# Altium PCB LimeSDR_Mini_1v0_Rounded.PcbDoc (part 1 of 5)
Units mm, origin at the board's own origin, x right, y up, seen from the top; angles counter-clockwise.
Board outline 69.3 x 52.3 mm, 8 copper layers (Top, L2, L3, L4, L5, L6, L7, Bottom), stack 1.555 mm thick; 371 components, 281 nets, 1644 pads, 778 vias.
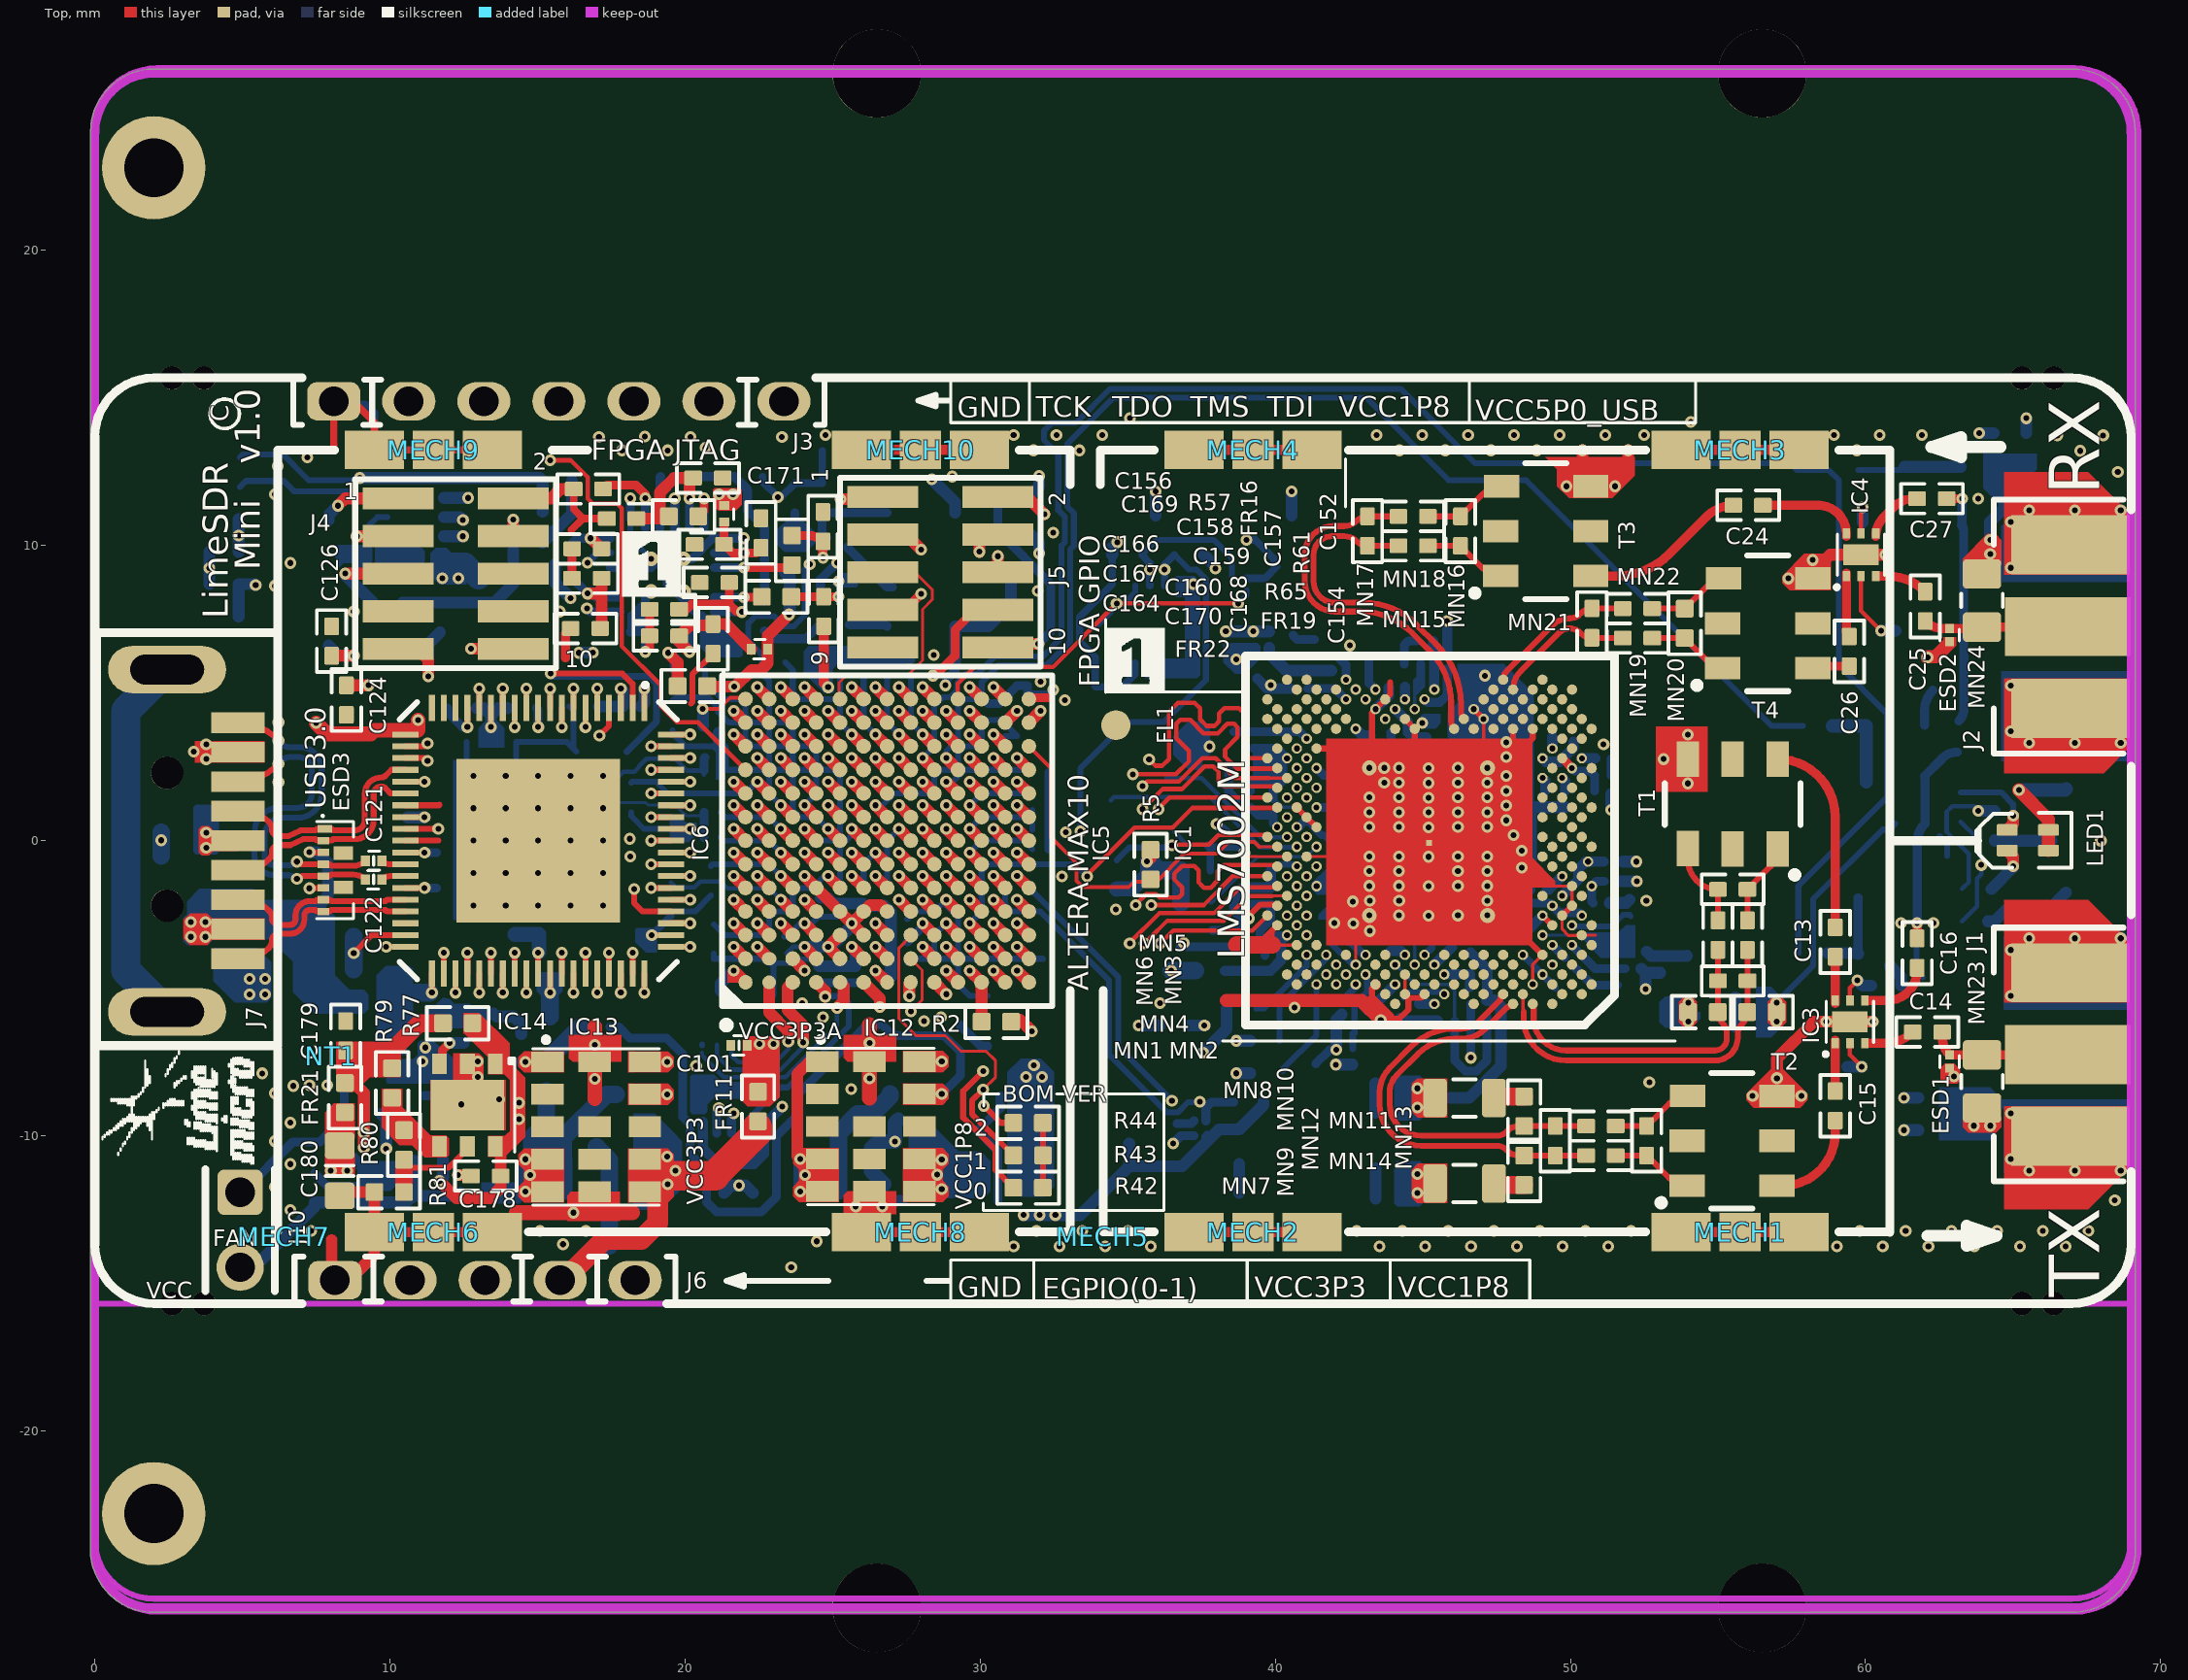
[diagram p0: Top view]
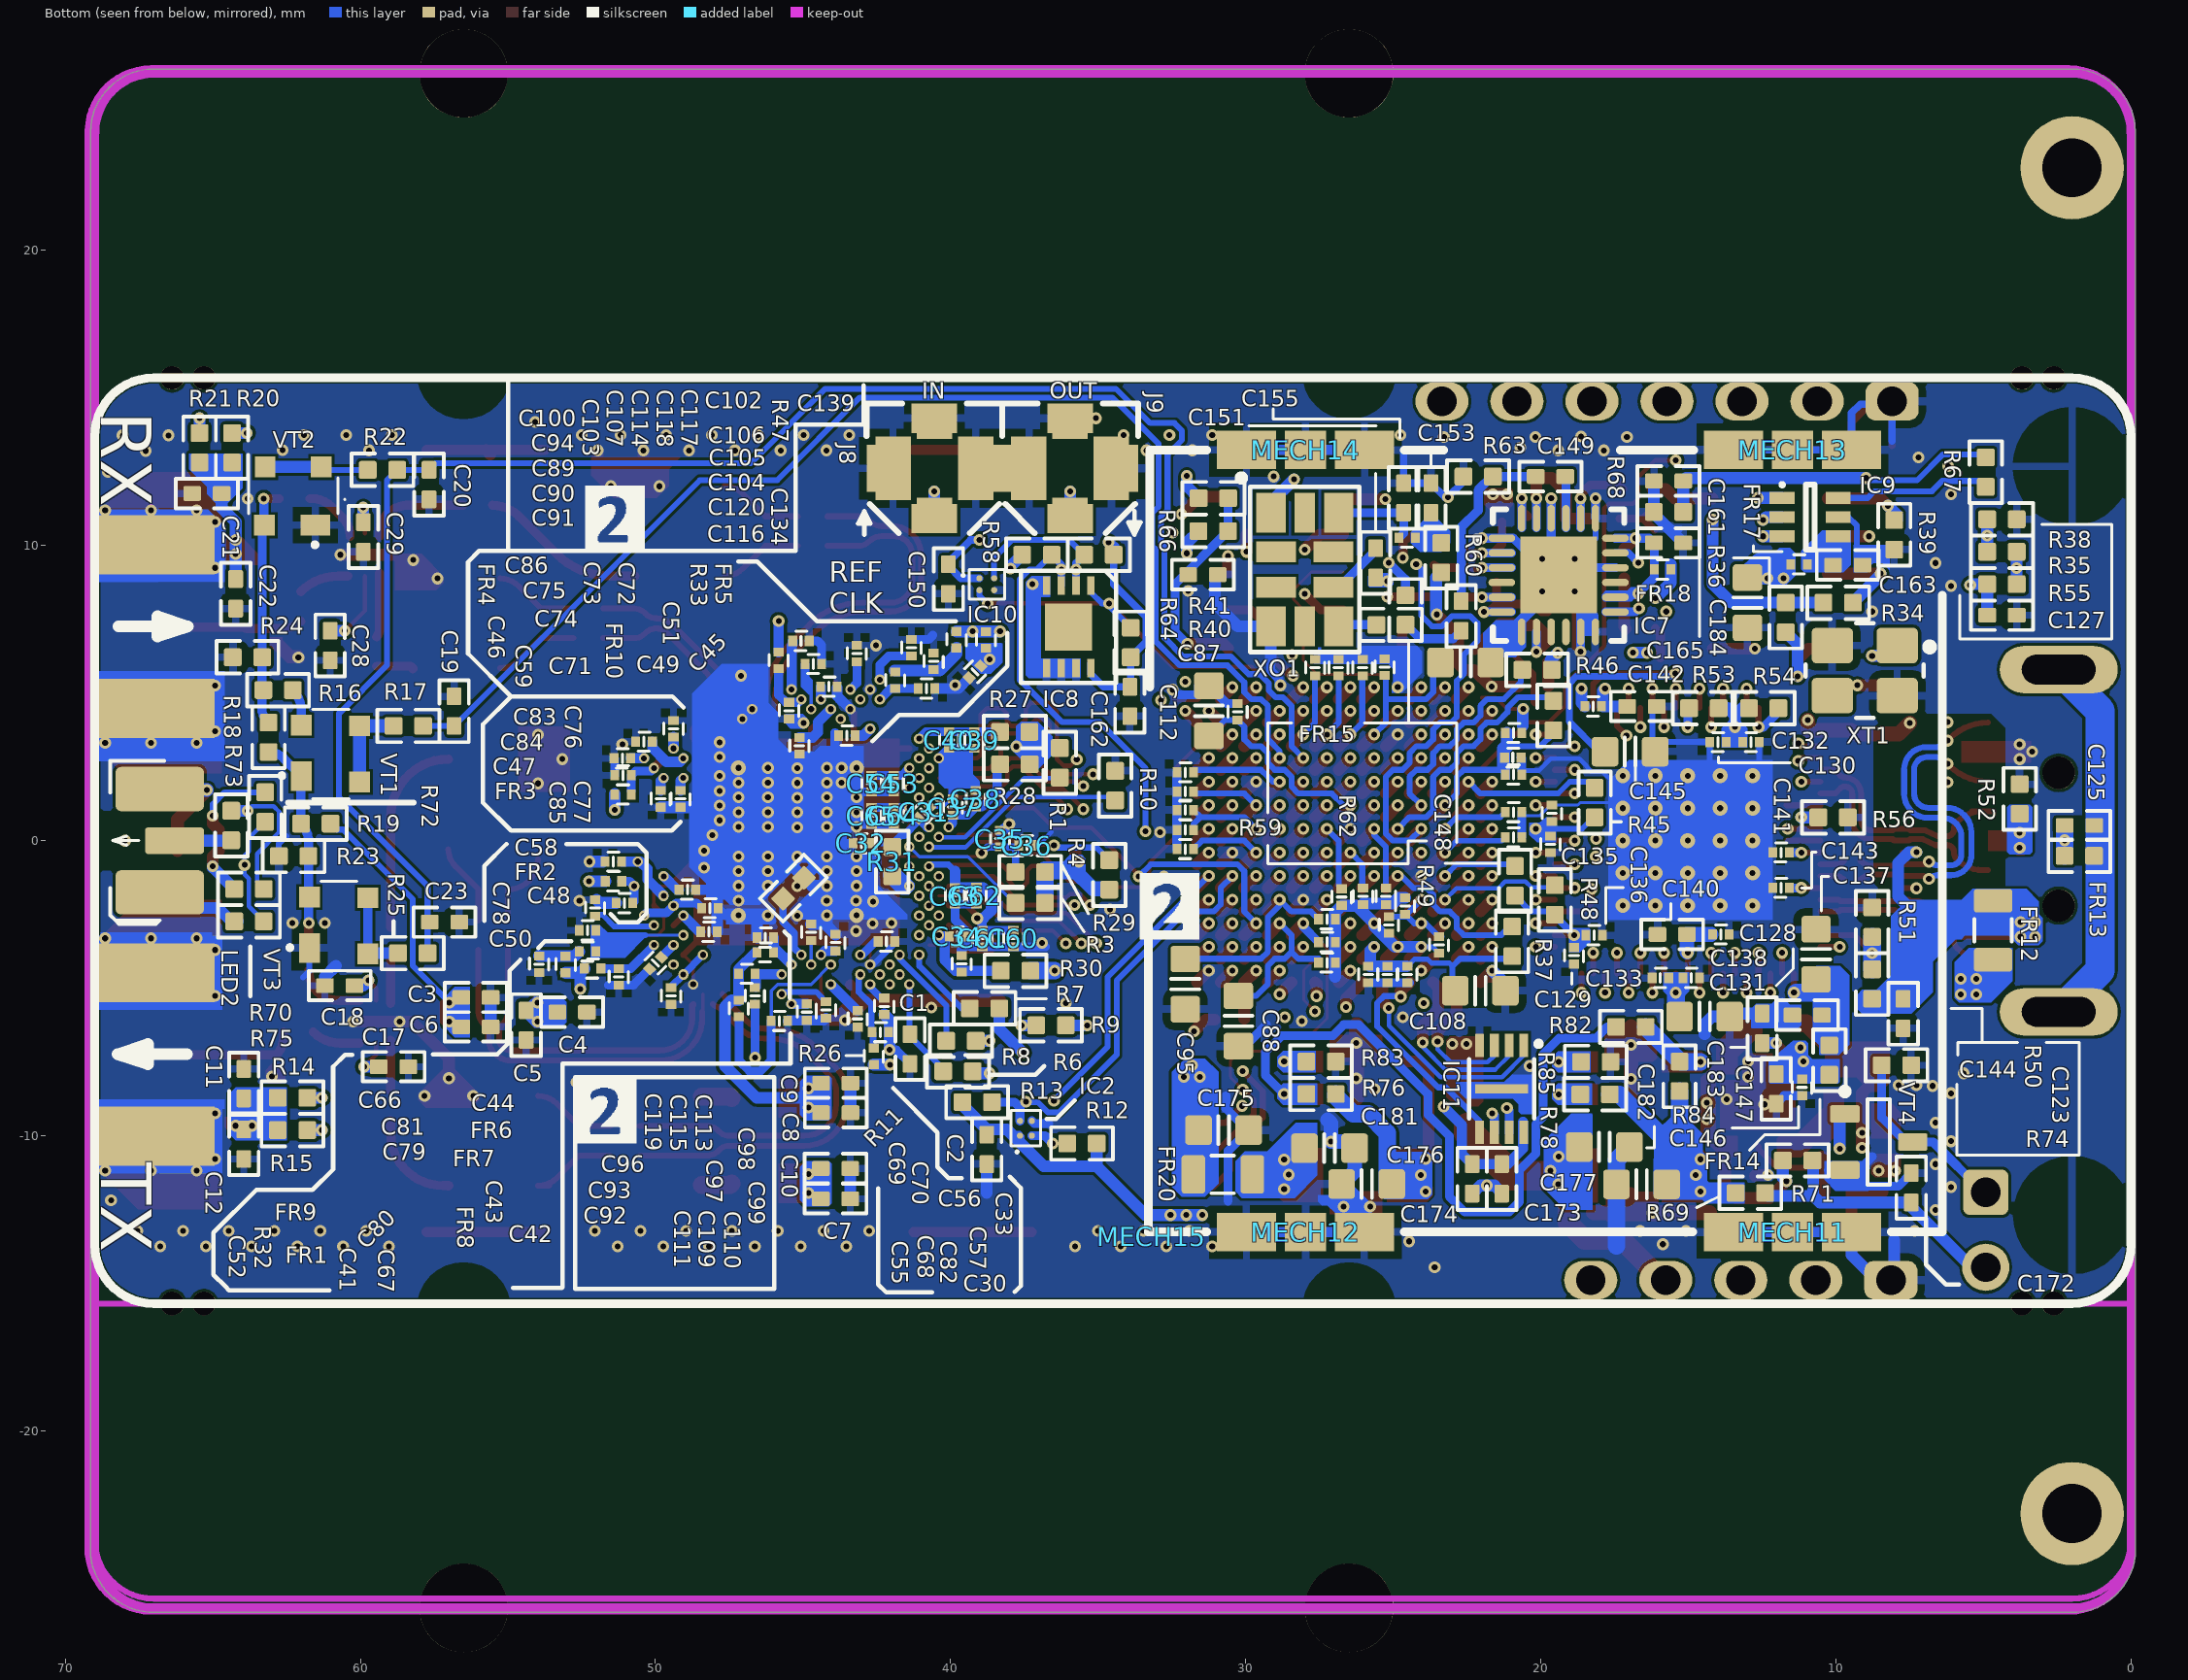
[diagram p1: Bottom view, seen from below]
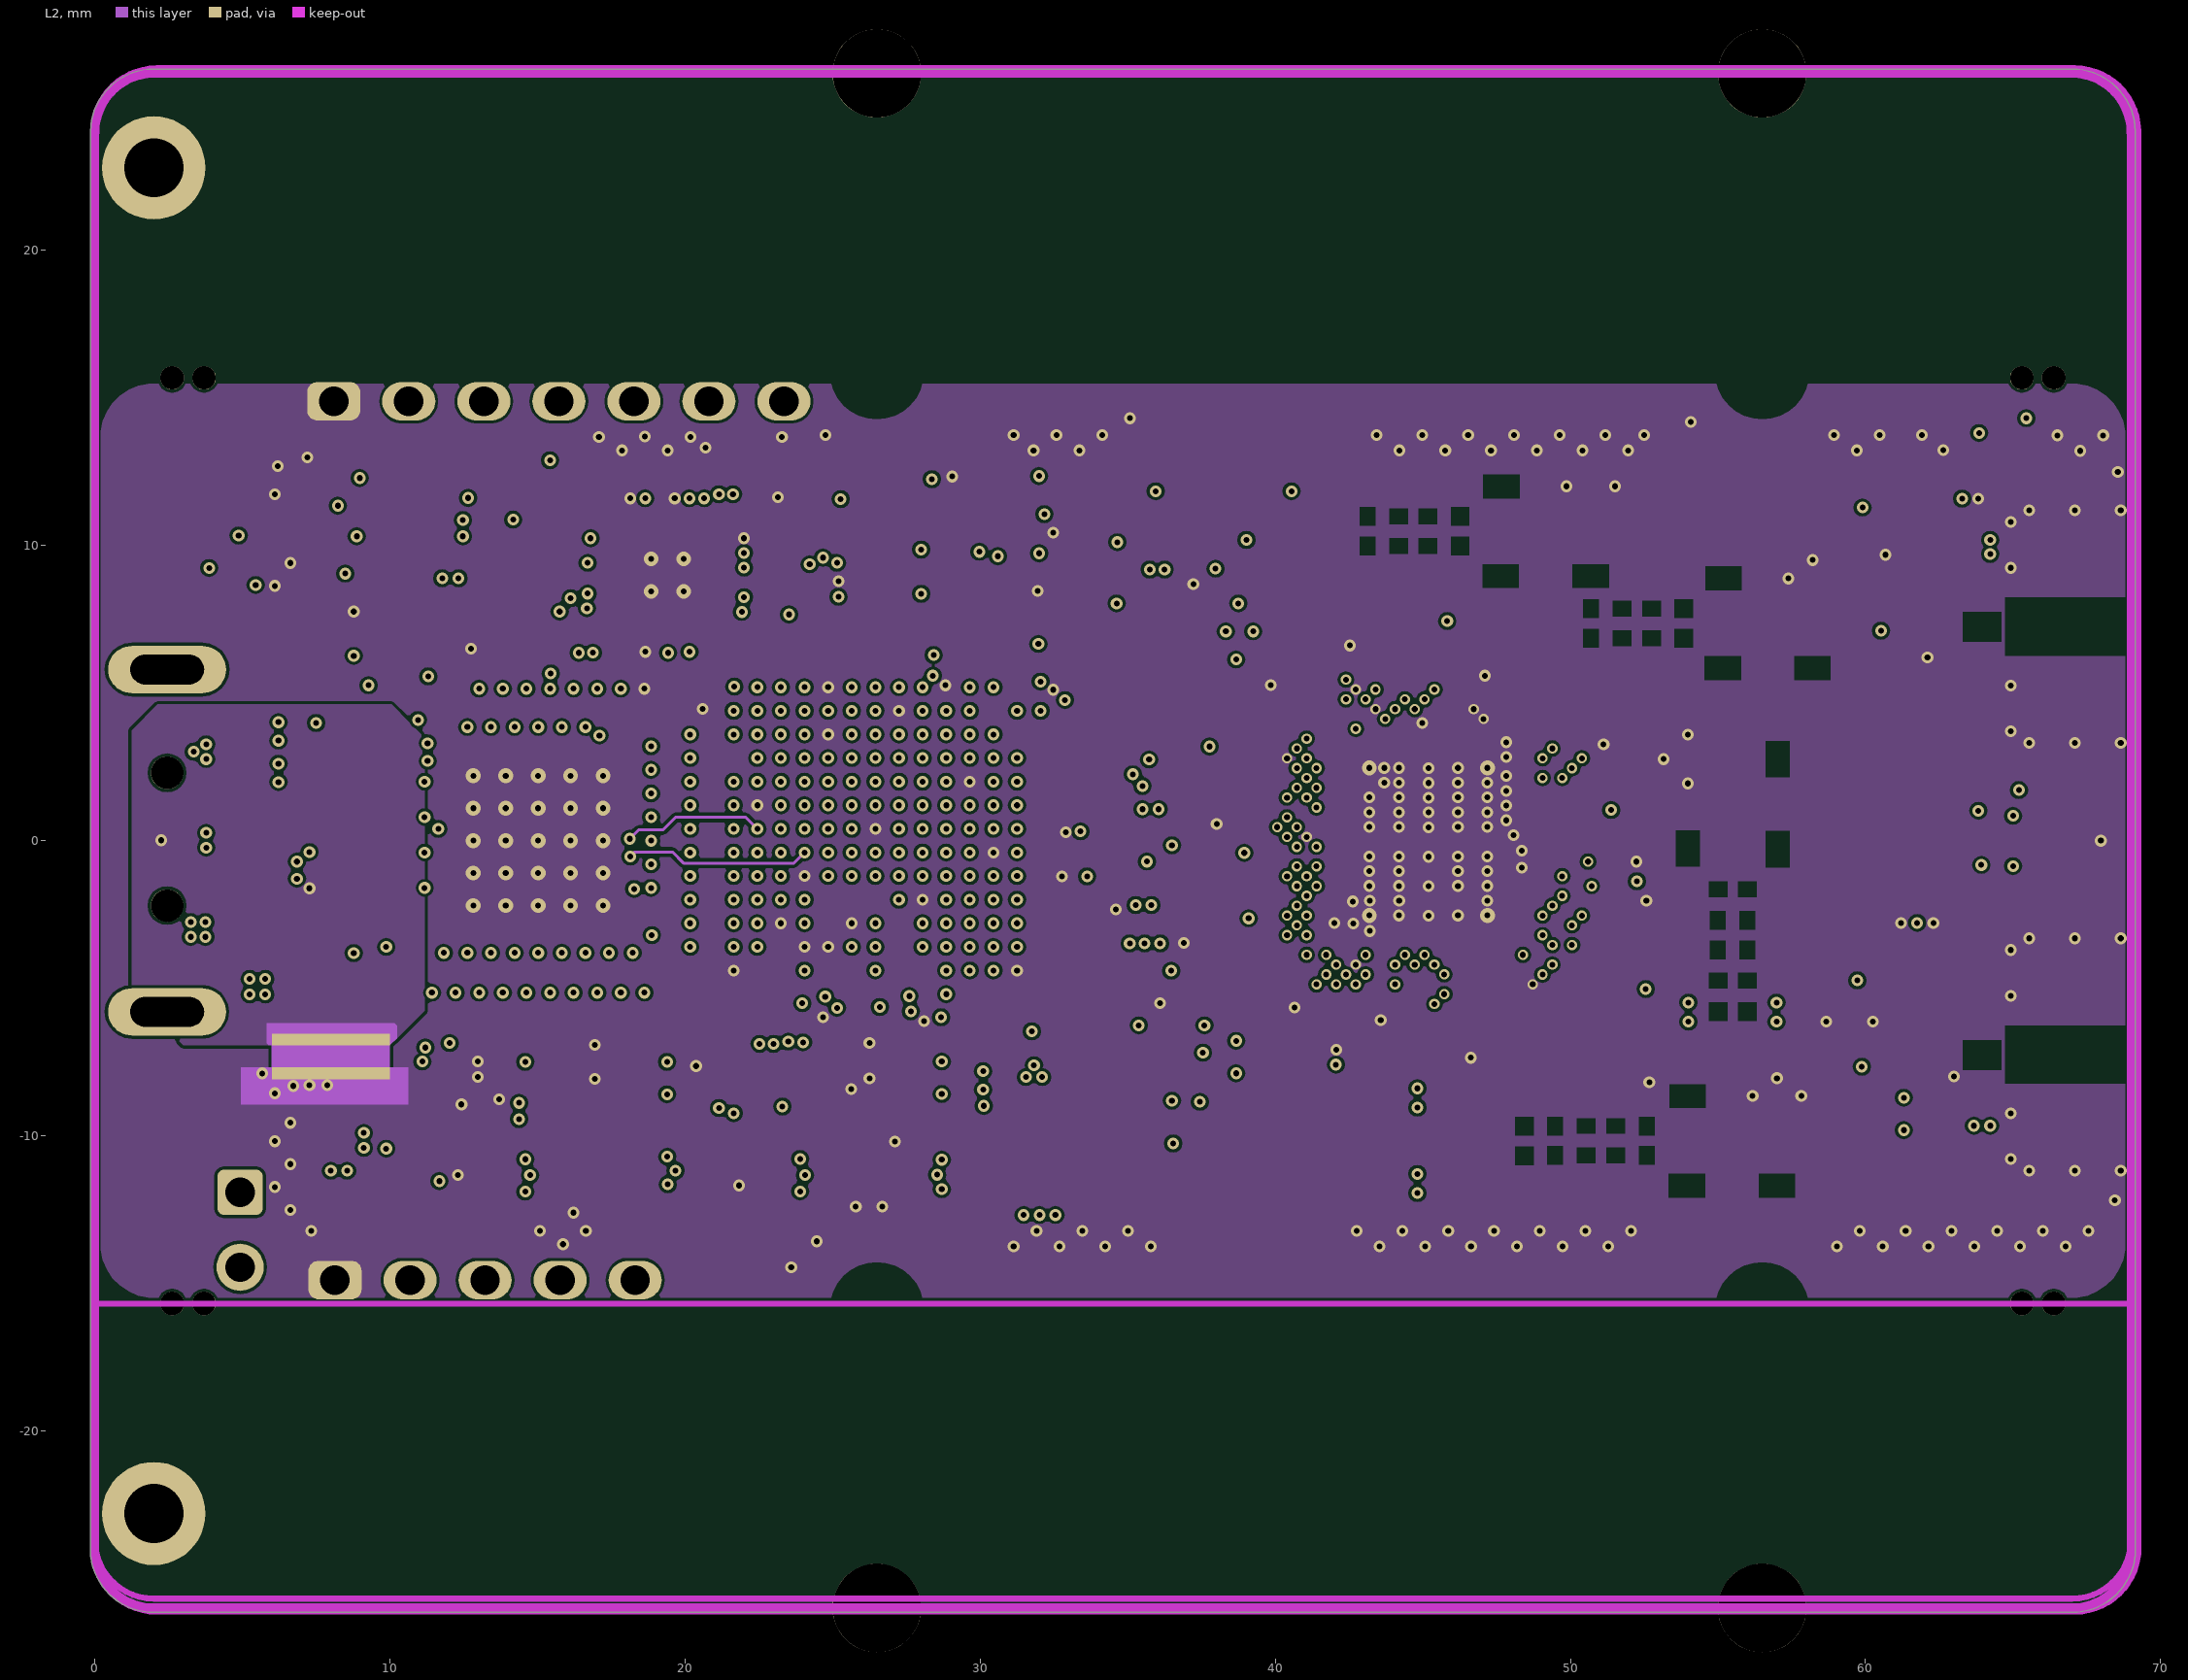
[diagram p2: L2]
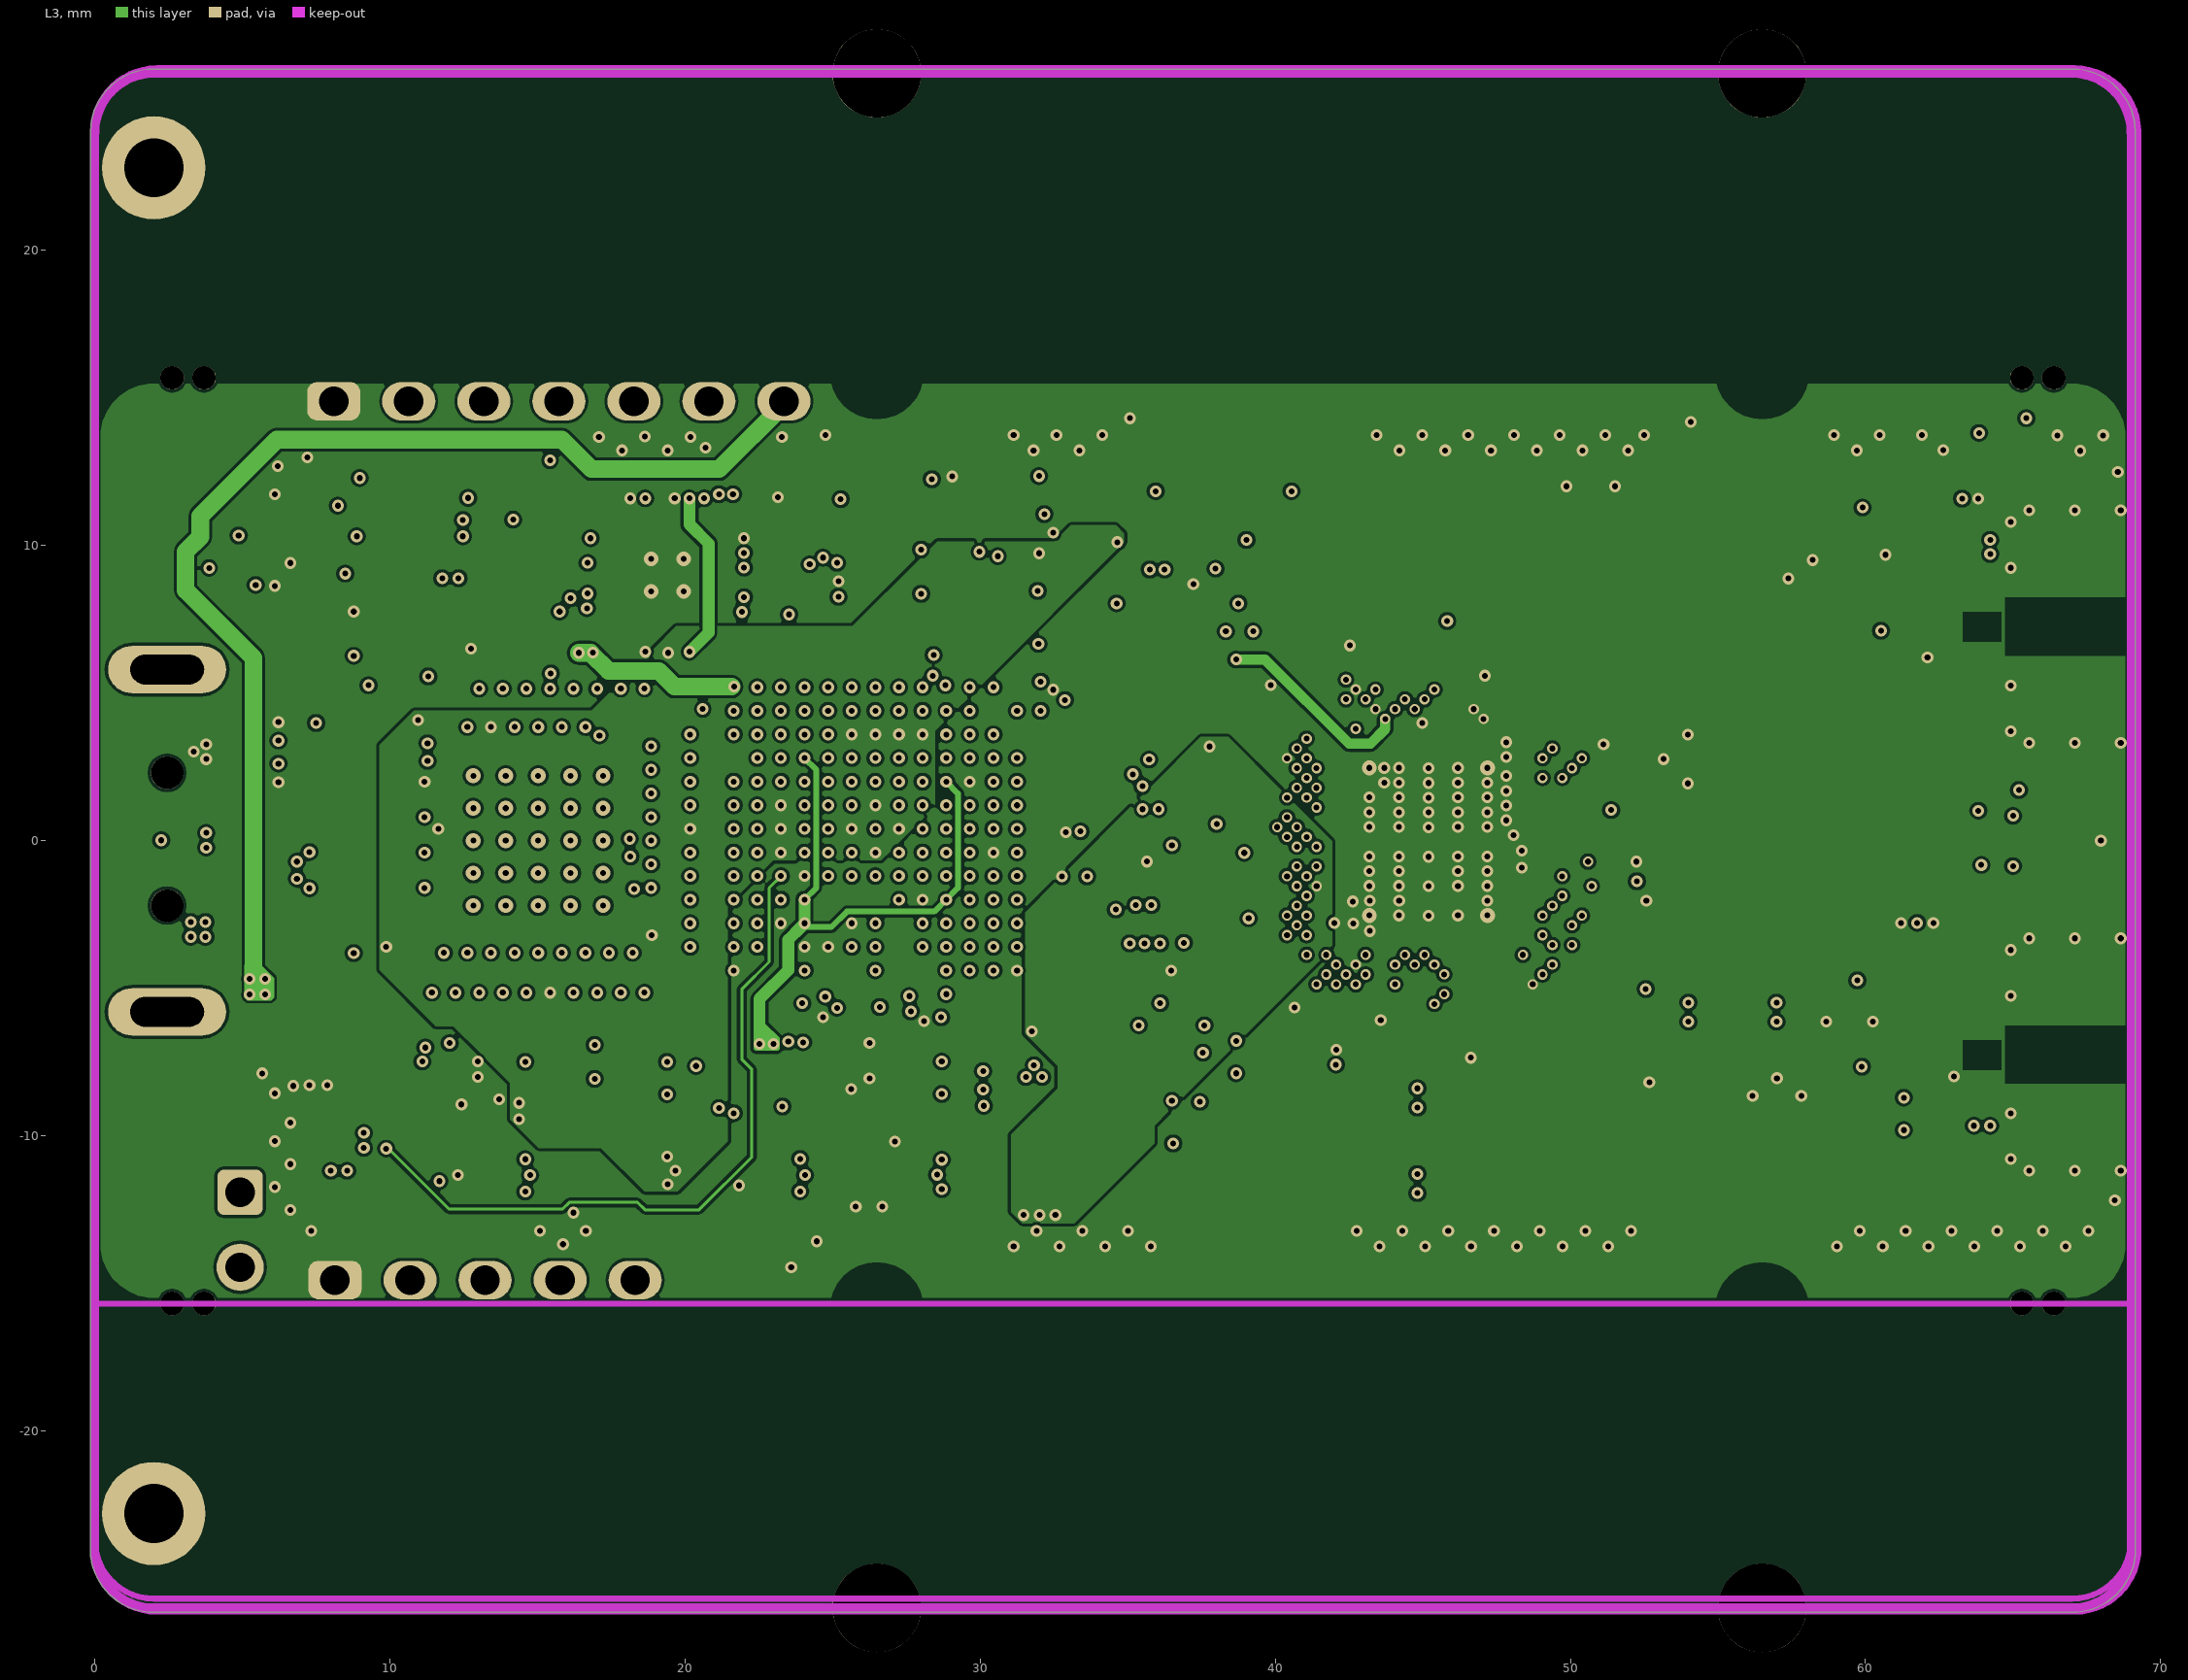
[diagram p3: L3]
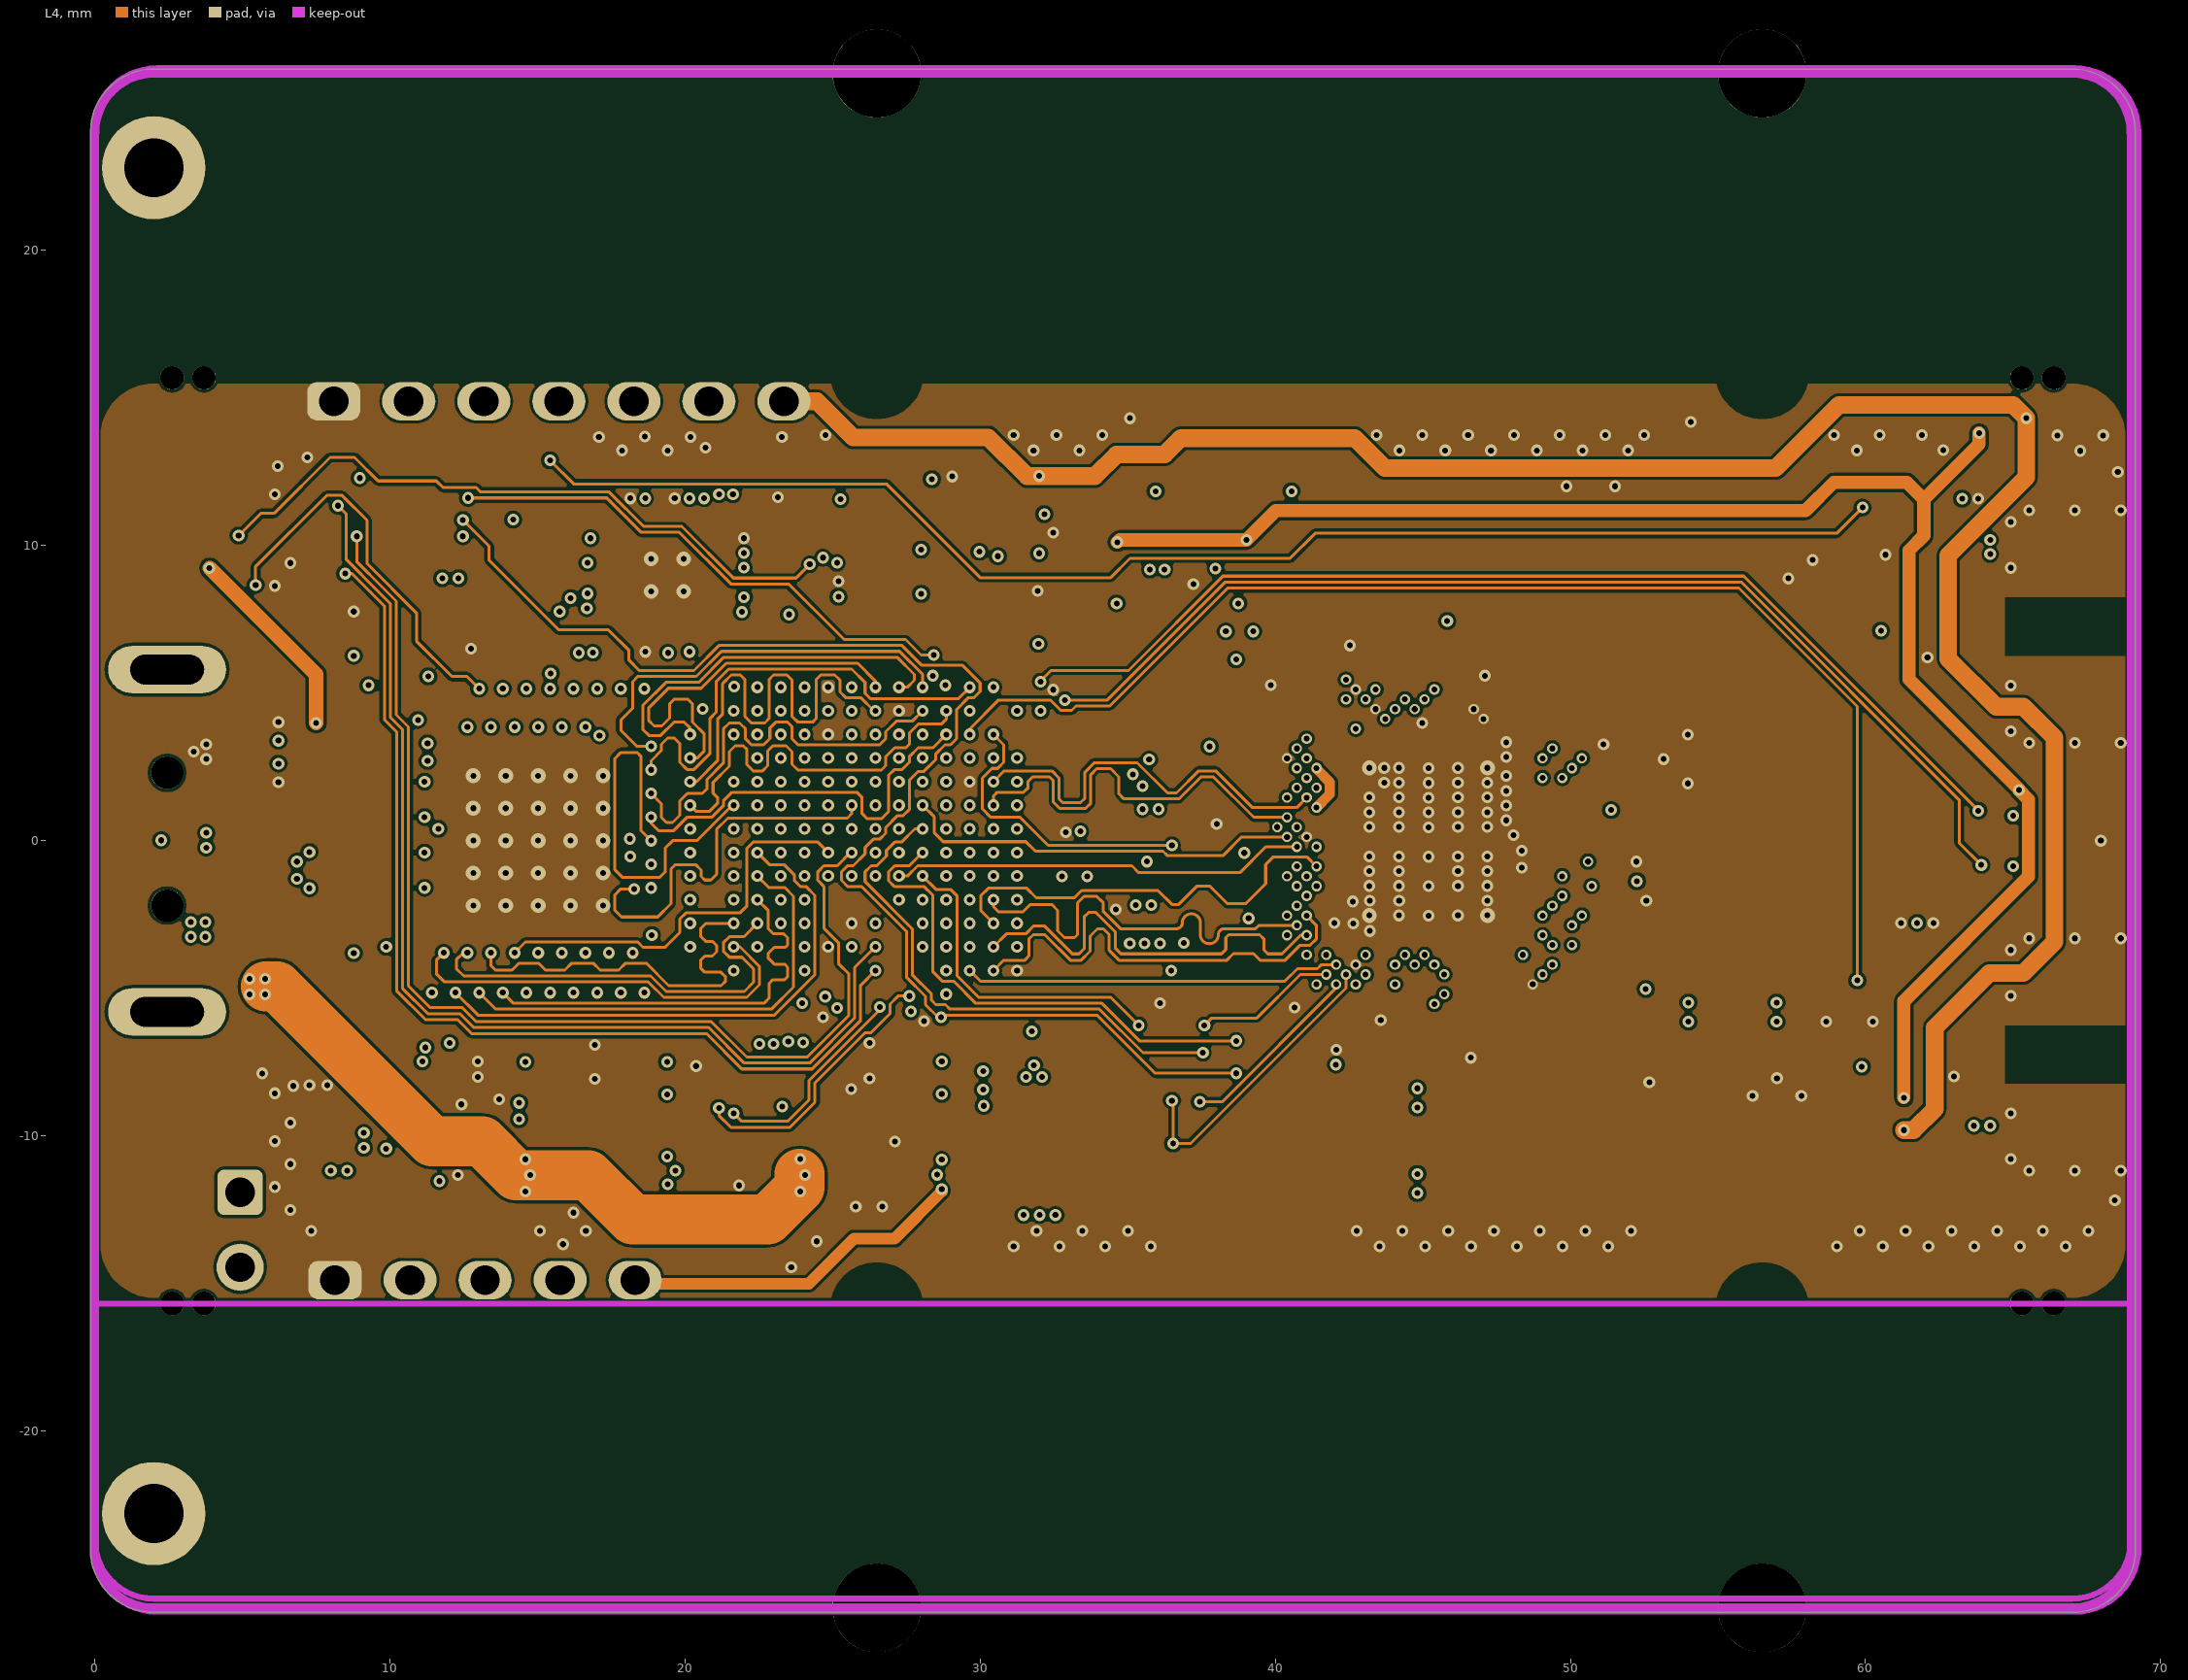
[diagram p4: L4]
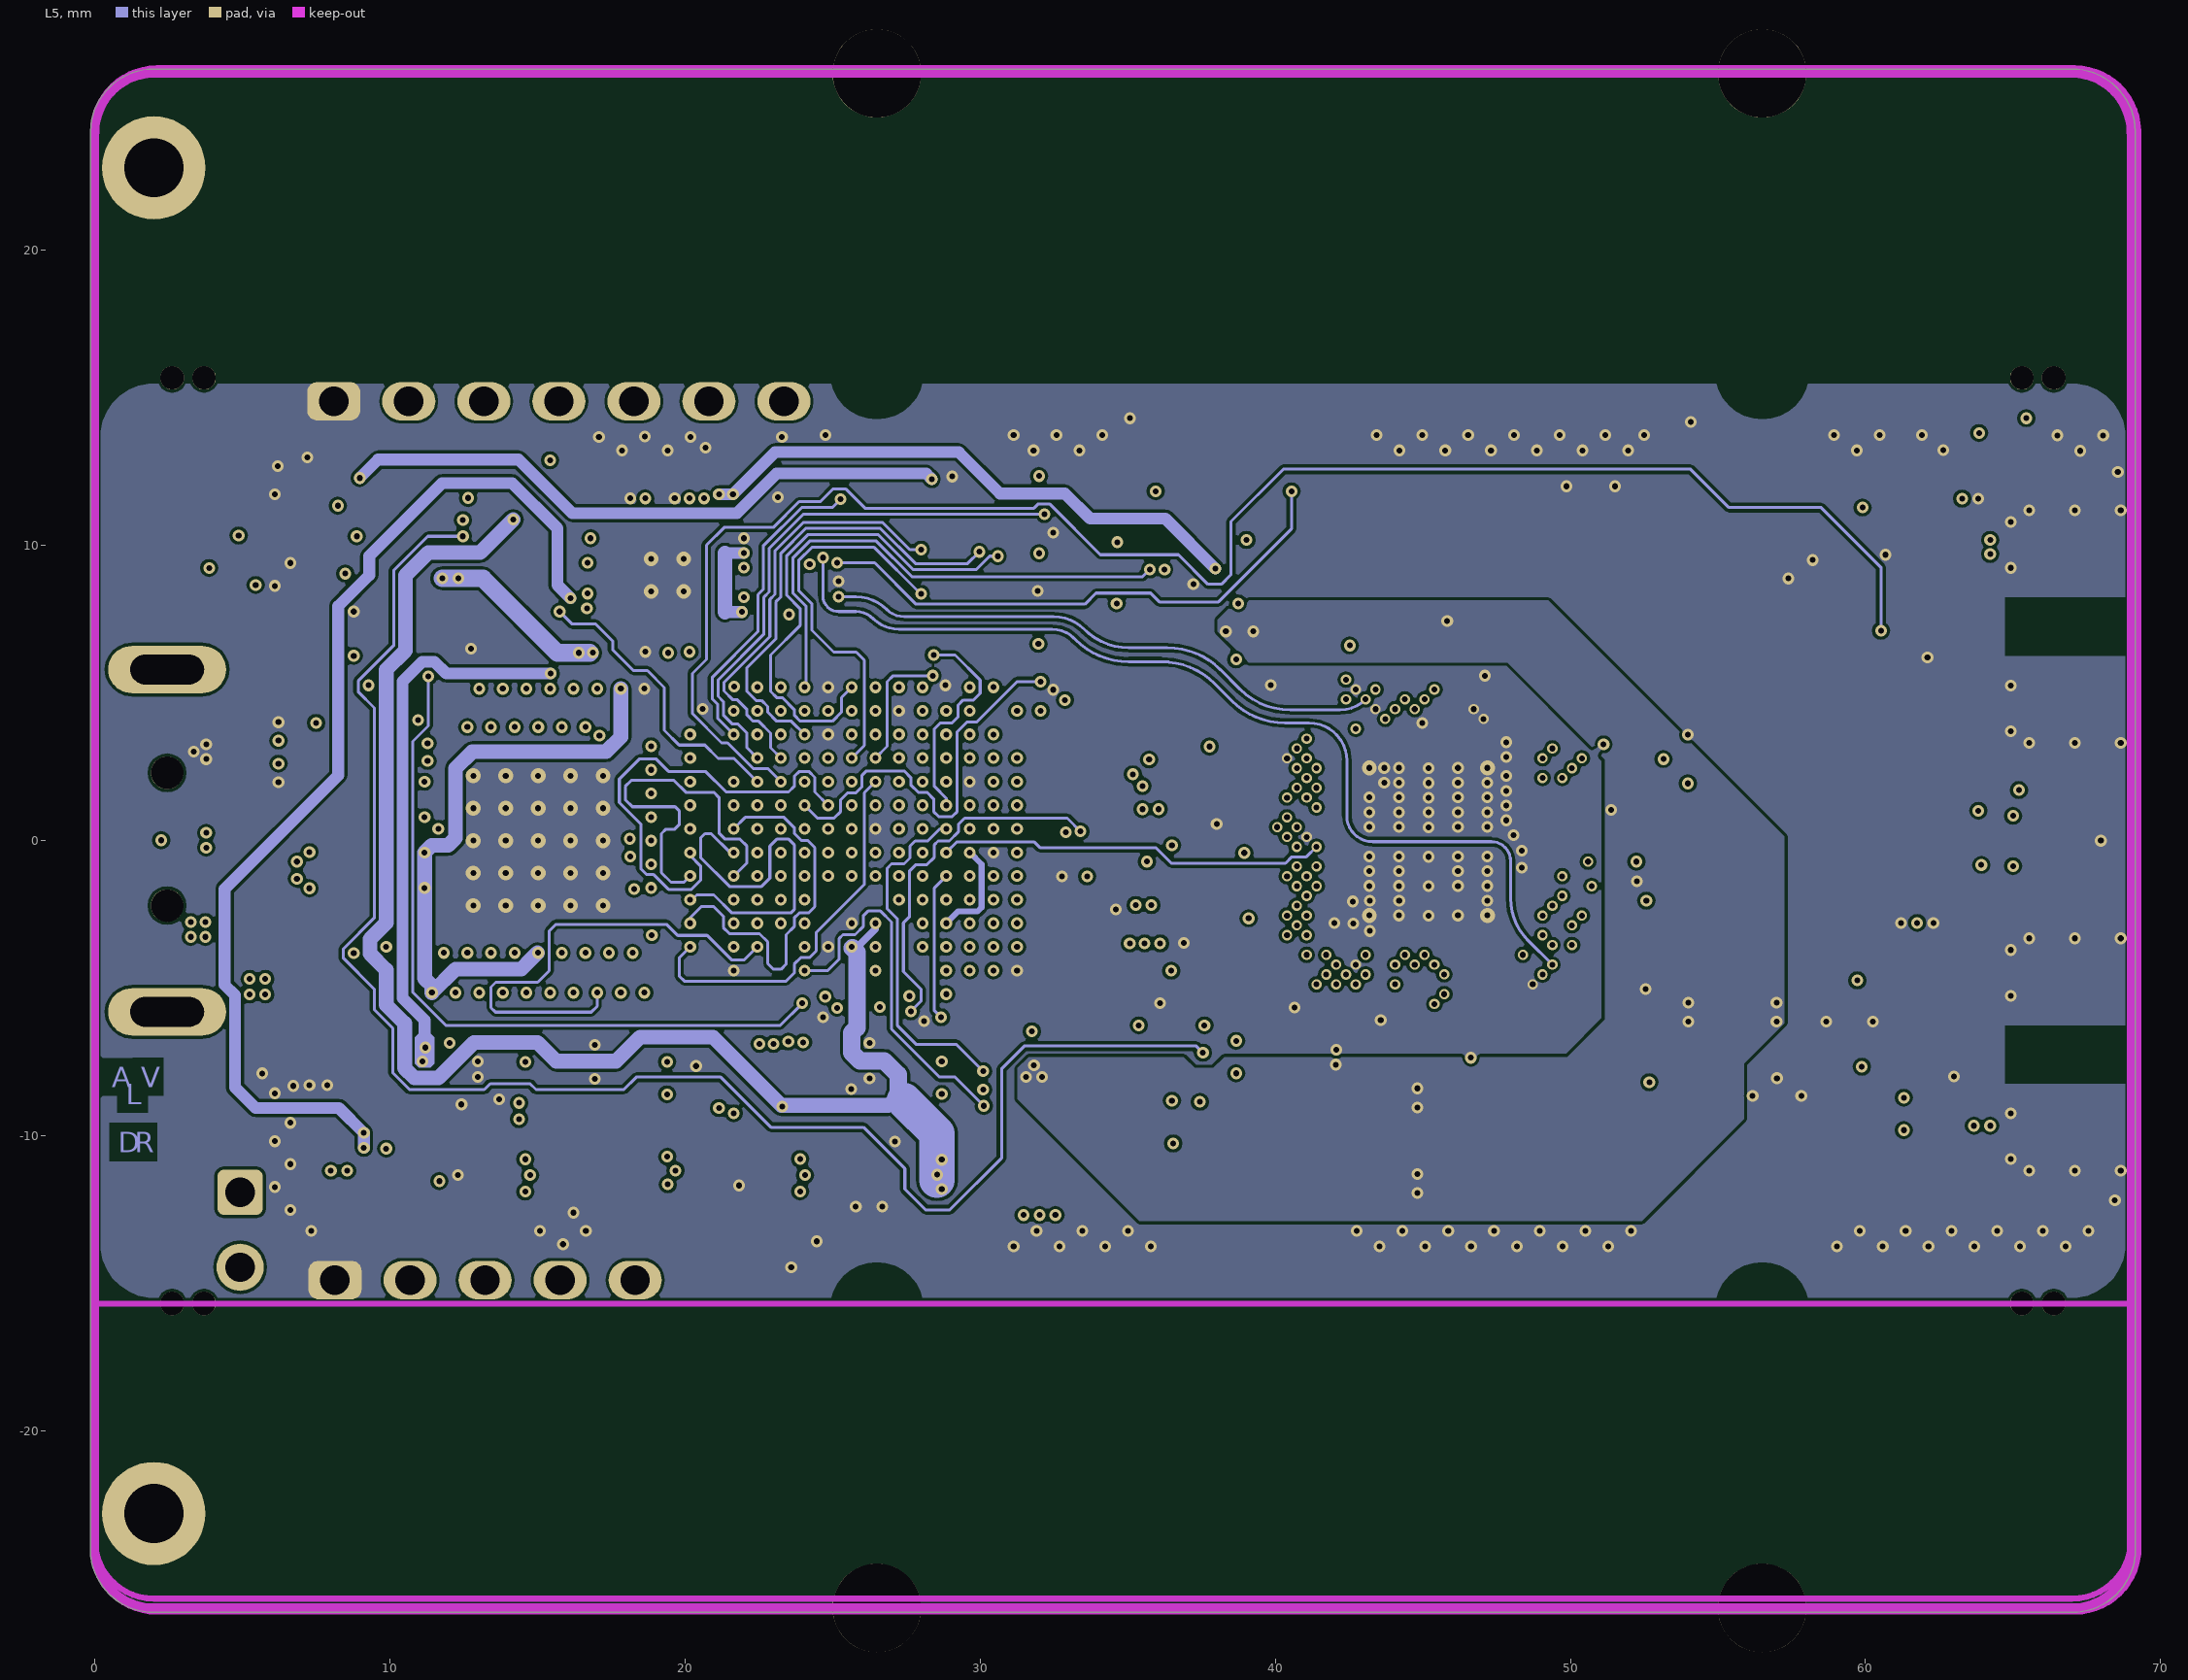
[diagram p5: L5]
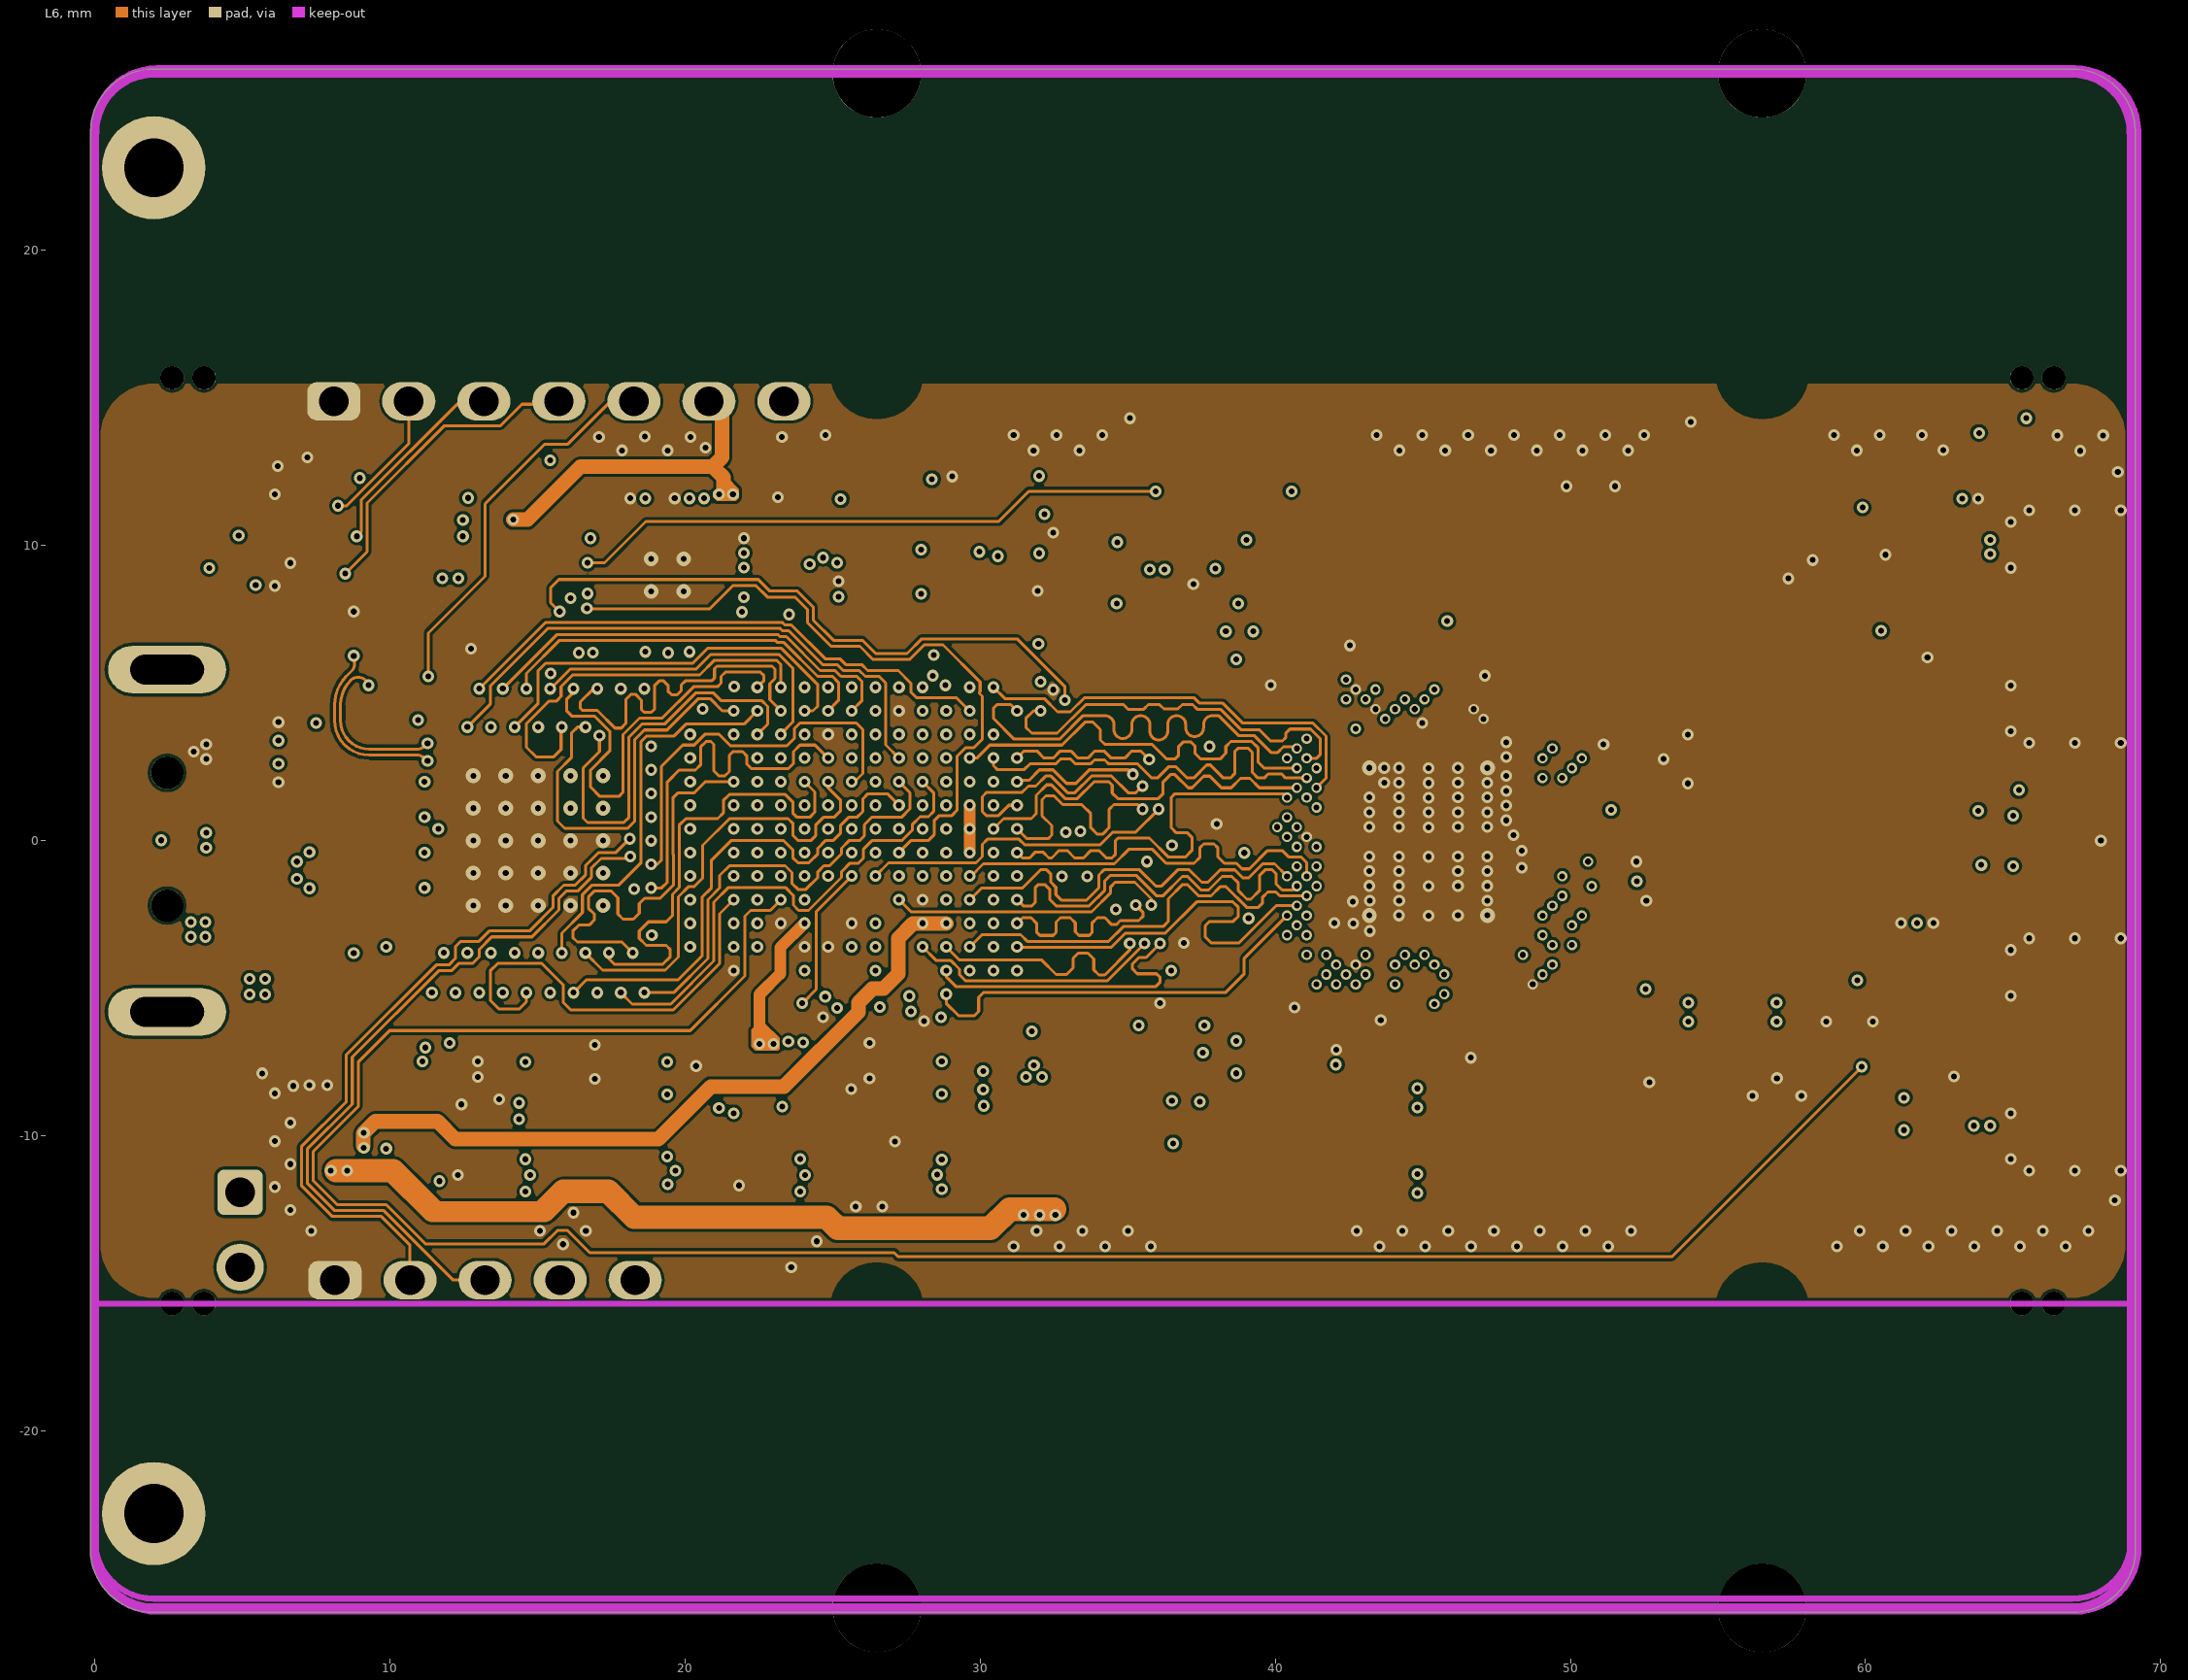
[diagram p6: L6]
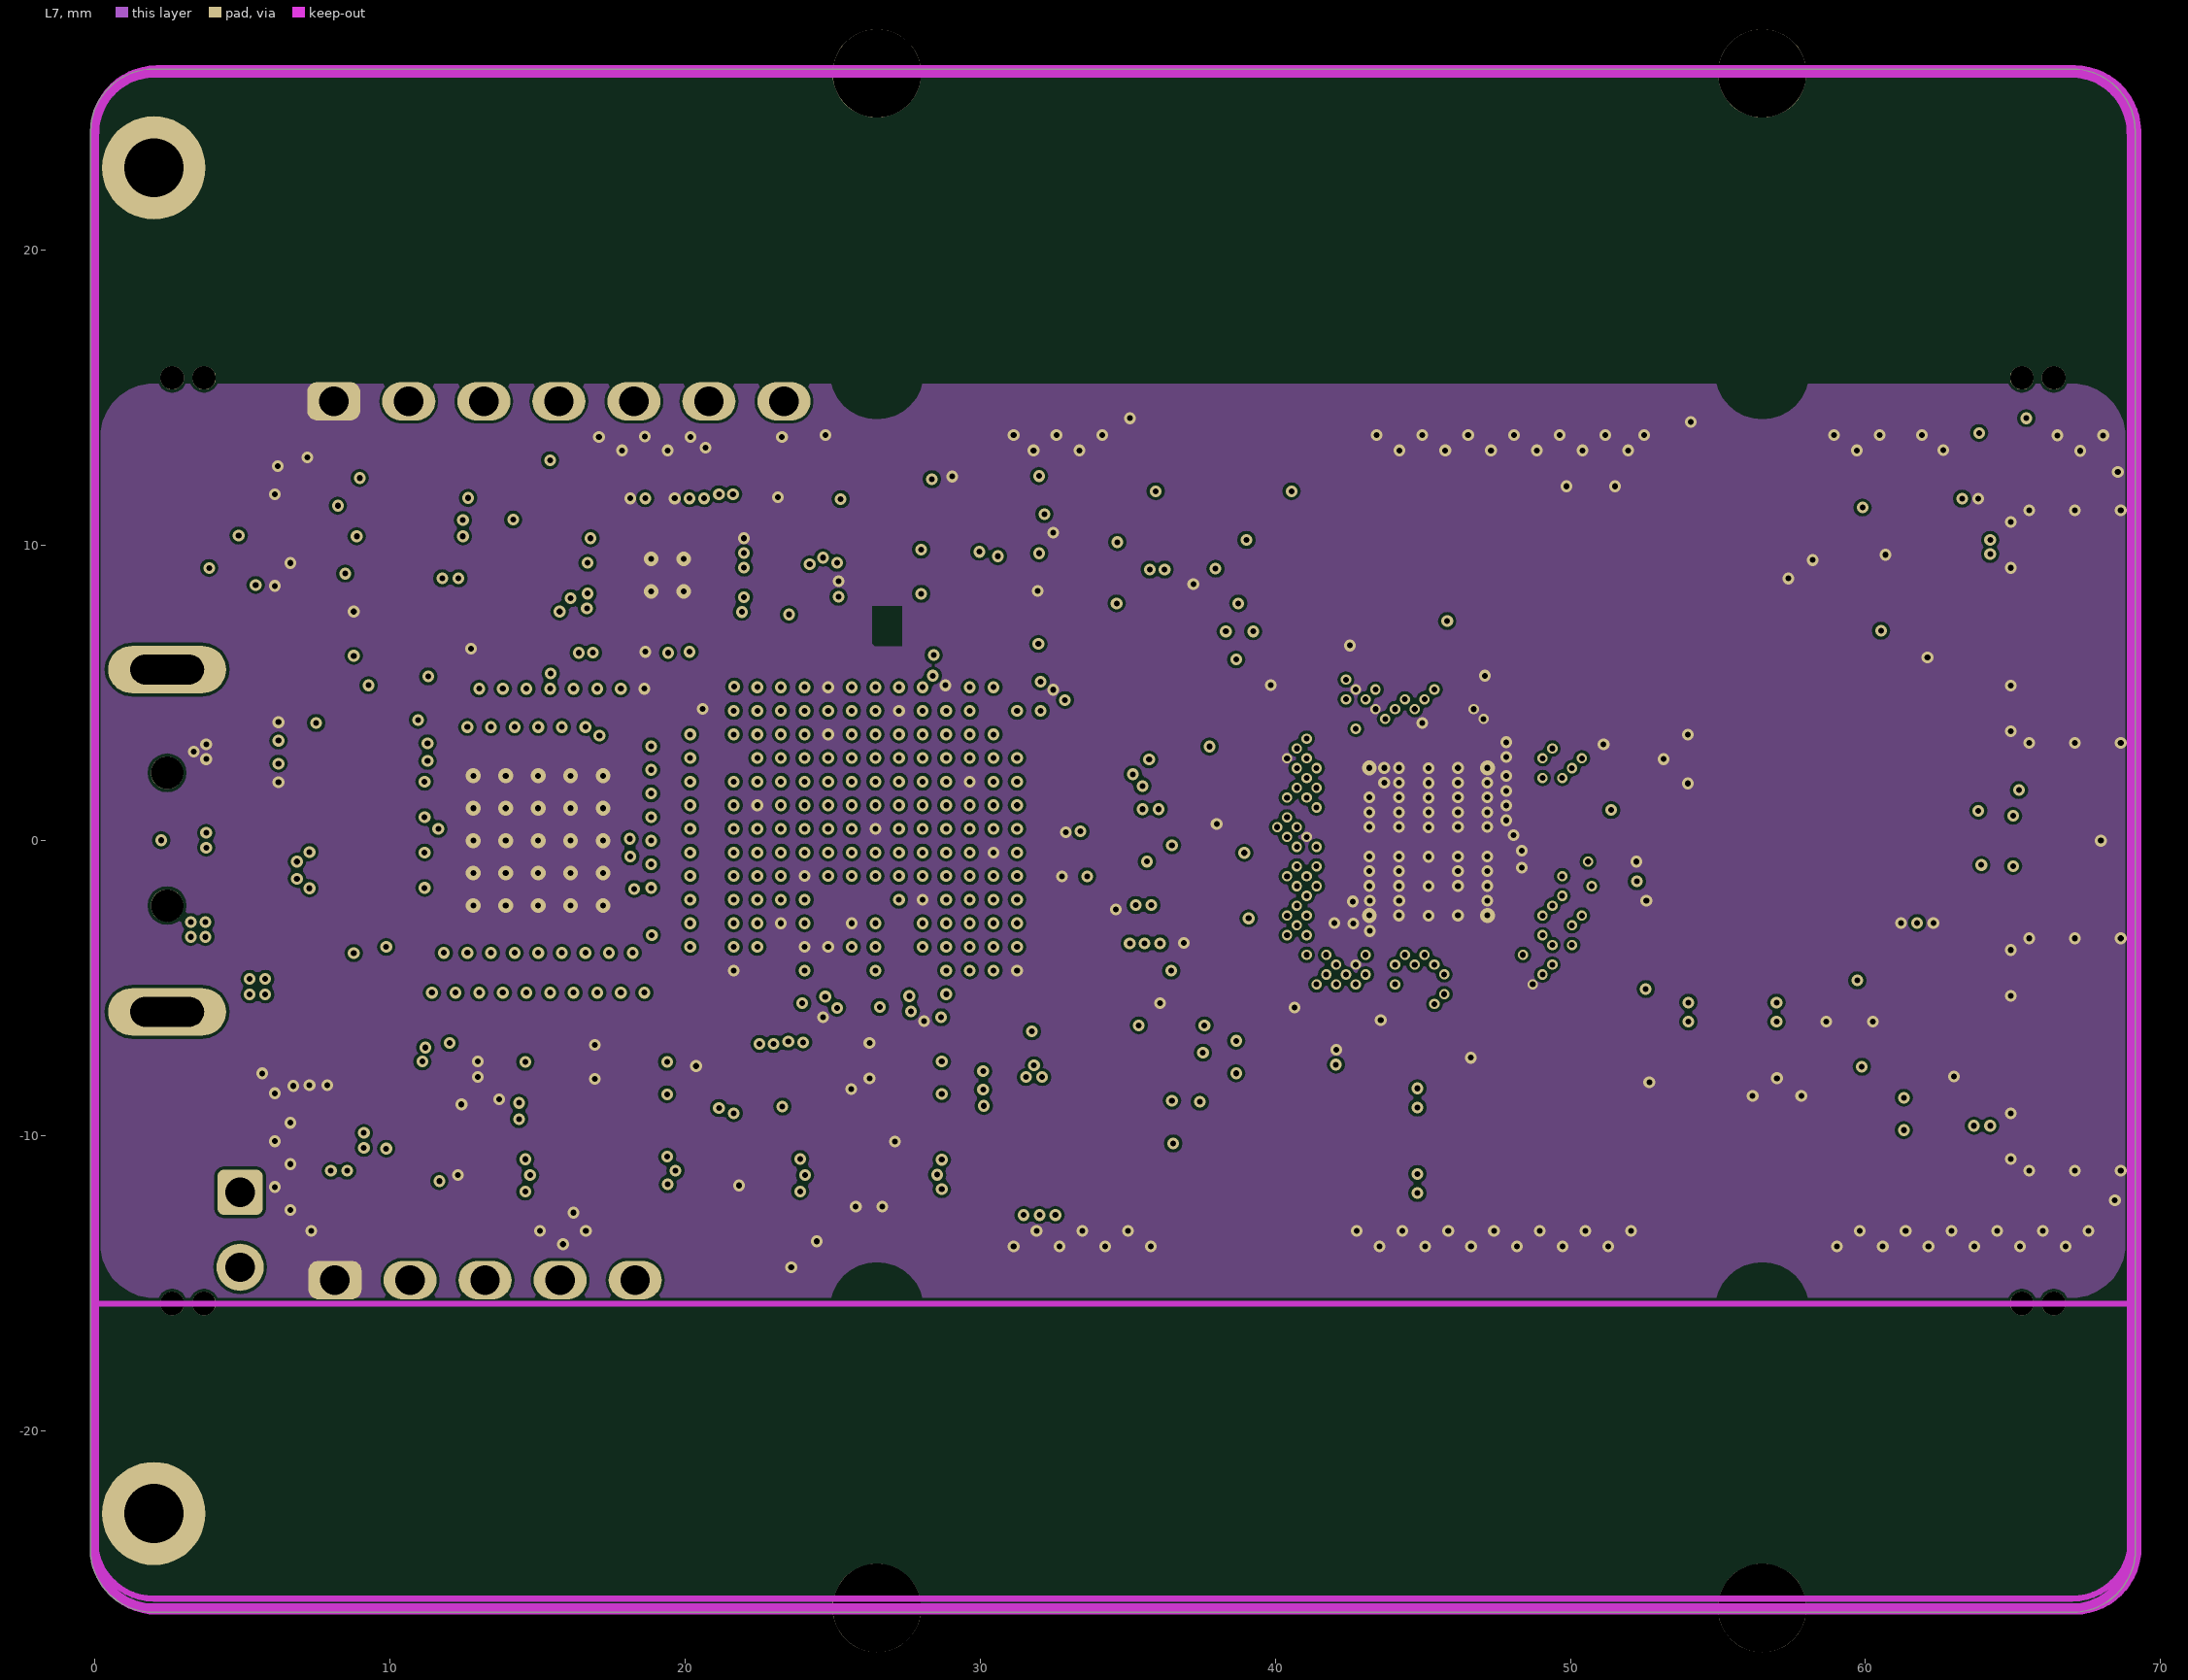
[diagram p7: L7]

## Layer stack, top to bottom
TopSolder: solder mask 0.0102, Solder Resist, Dk 3.5
Top: signal copper 0.0178
Dielectric1: core 0.17, FR-4, Dk 4.8
L2: signal copper 0.0356
Dielectric2: prepreg 0.3, FR-4, Dk 4.2
L3: signal copper 0.03
Dielectric3: core 0.2, FR-4, Dk 4.2
L4: signal copper 0.034
Dielectric 4: prepreg 0.2, Dk 4.2
L5: signal copper 0.03
Dielectric 10: core 0.09, Dk 4.2
L6: signal copper 0.03
Dielectric 11: prepreg 0.2, Dk 4.2
L7: signal copper 0.03
Dielectric 8: core 0.17, Dk 4.2
Bottom: signal copper 0.0178
BottomSolder: solder mask 0.0102, Solder Resist, Dk 3.5

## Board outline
-0.133,-24.269 cw(c0,-24.2) -0.15,-24.2 -0.15,24 cw(c0,24) -0.145,24.04 cw(c2.005,24) 2.005,26.15 66.995,26.15 cw(c66.995,24) 69.145,24.04 cw(c69,24) 69.15,24 69.15,-24.2 cw(c69,-24.2) 69.133,-24.269 cw(c67,-24) 67,-26.15 2,-26.15 cw(c2,-24)

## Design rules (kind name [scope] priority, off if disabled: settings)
BoardOutlineClearance [All] p1: gap=0.2
Clearance [All] p1: gap=0.1
ComponentClearance ComponentClearance_LNA_BYP [InComponent('R28') or InComponent('C22') or InComponent('R29') or InComponent('C20') vs InComponent('R28') or InComponent('C22') or InComponent('R29') or InComponent('C20')] p1: gap=-1 collisioncheckmode=3 verticalgap=2540 showdistances=FALSE
ComponentClearance ComponentClearance_CLK_RES [InComponent('R59') or InComponent('R62') vs InComponent('R59') or InComponent('R62')] p2: gap=-1 collisioncheckmode=3 verticalgap=2540 showdistances=FALSE
ComponentClearance ComponentClearance_RF_SHIELD [InComponent('MECH5') or InComponent('MECH7') or InComponent('MECH15')] p3: gap=-1 collisioncheckmode=3 verticalgap=2540 showdistances=FALSE
ComponentClearance [All] p4: gap=0.01 collisioncheckmode=3 verticalgap=0.254 showdistances=FALSE
DiffPairsRouting DiffPairsRouting_USB3 [InNetClass('FX3_DATA')] p1: maxlimit=0.3 minlimit=0.1 mostfreqgap=0.14 toplayer_minwidth=0.2 toplayer_maxwidth=0.2 toplayer_prefwidth=0.2 midlayer1_minwidth=0.2 midlayer1_maxwidth=0.2 midlayer1_prefwidth=0.2 midlayer2_minwidth=0.2 midlayer2_maxwidth=0.2 midlayer2_prefwidth=0.2 midlayer3_minwidth=0.2 midlayer3_maxwidth=0.2 midlayer3_prefwidth=0.2 midlayer4_minwidth=0.2 midlayer4_maxwidth=0.2 midlayer4_prefwidth=0.2 midlayer7_minwidth=0.2 midlayer7_maxwidth=0.2 midlayer7_prefwidth=0.2 midlayer9_minwidth=0.2 midlayer9_maxwidth=0.2 midlayer9_prefwidth=0.2 bottomlayer_minwidth=0.2 bottomlayer_maxwidth=0.2 bottomlayer_prefwidth=0.2 maxuncoupledlength=12.7
DiffPairsRouting DiffPairsRouting_USB3_XTAL [InNet('FX3_XTAL_N') or InNet('FX3_XTAL_P')] p2: maxlimit=0.2 minlimit=0.1 mostfreqgap=0.1 toplayer_minwidth=0.1 toplayer_maxwidth=0.4 toplayer_prefwidth=0.1 midlayer1_minwidth=0.1 midlayer1_maxwidth=0.4 midlayer1_prefwidth=0.1 midlayer2_minwidth=0.1 midlayer2_maxwidth=0.4 midlayer2_prefwidth=0.1 midlayer3_minwidth=0.1 midlayer3_maxwidth=0.4 midlayer3_prefwidth=0.1 midlayer4_minwidth=0.1 midlayer4_maxwidth=0.4 midlayer4_prefwidth=0.1 midlayer7_minwidth=0.1 midlayer7_maxwidth=0.4 midlayer7_prefwidth=0.1 midlayer9_minwidth=0.1 midlayer9_maxwidth=0.4 midlayer9_prefwidth=0.1 bottomlayer_minwidth=0.1 bottomlayer_maxwidth=0.4 bottomlayer_prefwidth=0.1 maxuncoupledlength=0.2
DiffPairsRouting DiffPairsRouting_TX_RF [InNetClass('TX_RF')] p3: maxlimit=0.14 minlimit=0.14 mostfreqgap=0.14 toplayer_minwidth=0.1 toplayer_maxwidth=0.2 toplayer_prefwidth=0.2 midlayer1_minwidth=0.1 midlayer1_maxwidth=0.2 midlayer1_prefwidth=0.2 midlayer2_minwidth=0.1 midlayer2_maxwidth=0.2 midlayer2_prefwidth=0.2 midlayer3_minwidth=0.1 midlayer3_maxwidth=0.2 midlayer3_prefwidth=0.2 midlayer4_minwidth=0.1 midlayer4_maxwidth=0.2 midlayer4_prefwidth=0.2 midlayer7_minwidth=0.1 midlayer7_maxwidth=0.2 midlayer7_prefwidth=0.2 midlayer9_minwidth=0.1 midlayer9_maxwidth=0.2 midlayer9_prefwidth=0.2 bottomlayer_minwidth=0.1 bottomlayer_maxwidth=0.2 bottomlayer_prefwidth=0.2 maxuncoupledlength=0.2
DiffPairsRouting DiffPairsRouting_RX_RF [InNetClass('RX_RF')] p4: maxlimit=0.3 minlimit=0.1 mostfreqgap=0.14 toplayer_minwidth=0.1 toplayer_maxwidth=0.3 toplayer_prefwidth=0.2 midlayer1_minwidth=0.1 midlayer1_maxwidth=0.3 midlayer1_prefwidth=0.2 midlayer2_minwidth=0.1 midlayer2_maxwidth=0.3 midlayer2_prefwidth=0.2 midlayer3_minwidth=0.1 midlayer3_maxwidth=0.3 midlayer3_prefwidth=0.2 midlayer4_minwidth=0.1 midlayer4_maxwidth=0.3 midlayer4_prefwidth=0.2 midlayer7_minwidth=0.1 midlayer7_maxwidth=0.3 midlayer7_prefwidth=0.2 midlayer9_minwidth=0.1 midlayer9_maxwidth=0.3 midlayer9_prefwidth=0.2 bottomlayer_minwidth=0.1 bottomlayer_maxwidth=0.3 bottomlayer_prefwidth=0.2 maxuncoupledlength=0.2
DiffPairsRouting [All] p5: maxlimit=0.3 minlimit=0.1 mostfreqgap=0.1 toplayer_minwidth=0.1 toplayer_maxwidth=0.5 toplayer_prefwidth=0.2 midlayer1_minwidth=0.1 midlayer1_maxwidth=0.5 midlayer1_prefwidth=0.2 midlayer2_minwidth=0.1 midlayer2_maxwidth=0.5 midlayer2_prefwidth=0.2 midlayer3_minwidth=0.1 midlayer3_maxwidth=0.5 midlayer3_prefwidth=0.2 midlayer4_minwidth=0.1 midlayer4_maxwidth=0.5 midlayer4_prefwidth=0.2 midlayer7_minwidth=0.1 midlayer7_maxwidth=0.5 midlayer7_prefwidth=0.2 midlayer9_minwidth=0.1 midlayer9_maxwidth=0.5 midlayer9_prefwidth=0.2 bottomlayer_minwidth=0.1 bottomlayer_maxwidth=0.5 bottomlayer_prefwidth=0.2 maxuncoupledlength=12.7
FabricationTestPointUsage TestPointUsage [All] p1: valid=0 allowmultiple=FALSE
FabricationTestpoint Testpoint [All] p1: side=3 testpointundercomponent=TRUE minsize=1.016 maxsize=2.54 preferedsize=1.524 minholesize=0.508 maxholesize=1.016 preferedholesize=0.813 testpointgrid=0.025 allowsidetop=TRUE allowsidebottom=TRUE usegrid=TRUE gridtolerance=0
HoleSize [All] p1: absolutevalues=TRUE maxlimit=10 minlimit=0.2 maxpercent=80.000 minpercent=20.000
HoleToHoleClearance [All] p1: gap=0.15 allowstackedmicrovias=TRUE
MatchedLengths MatchedLengths_FT_FIFO [InNetClass('FT_FIFO')] p1: tolerance=5 checknetsindiffpair=FALSE checkdiffpairvsdiffpair=TRUE checkxsignals=TRUE checkothers=TRUE
MatchedLengths MatchedLengths_LMS_PORT1 [InNetClass('LMS_PORT1')] p2: tolerance=7 checknetsindiffpair=FALSE checkdiffpairvsdiffpair=TRUE checkxsignals=TRUE checkothers=TRUE // tolerance increased due to MCLK being longer
MatchedLengths MatchedLengths_LMS_PORT2 [InNetClass('LMS_PORT2')] p3: tolerance=7.5 checknetsindiffpair=FALSE checkdiffpairvsdiffpair=TRUE checkxsignals=TRUE checkothers=TRUE // tolerance increased due to MCLK being longer
PlaneClearance [All] p1: clearance=0
PolygonConnect PolygonConnect_VCC3P3 [InNetClass('VCC3P3')] p1: connectstyle=Direct reliefconductorwidth=0.254 reliefentries=4 polygonreliefangle="90 Angle" airgapwidth=0.254
PolygonConnect PolygonConnect_GND_VIA [InNet('GND') and isvia] p2: connectstyle=Direct reliefconductorwidth=0.254 reliefentries=4 polygonreliefangle="90 Angle" airgapwidth=0.254
PolygonConnect PolygonConnect_GND_MMCX [HasFootprint('MMCX_UFL_CONN_V3_M') and IsPad and InNet('GND')] p3: connectstyle=Relief reliefconductorwidth=0.7 reliefentries=4 polygonreliefangle="90 Angle" airgapwidth=0.254
PolygonConnect PolygonConnect_GND [InNet('GND') and (OnTopLayer or OnBottomLayer)] p4: connectstyle=Relief reliefconductorwidth=0.254 reliefentries=4 polygonreliefangle="90 Angle" airgapwidth=0.254
PolygonConnect PolygonConnect_GND_inner [InNet('GND') and not (OnTopLayer or OnBottomLayer)] p5: connectstyle=Direct reliefconductorwidth=0.254 reliefentries=4 polygonreliefangle="90 Angle" airgapwidth=0.254
PolygonConnect PolygonConnect_USB_GND [InNet('USB_GND')] p6: connectstyle=Direct reliefconductorwidth=0.254 reliefentries=4 polygonreliefangle="90 Angle" airgapwidth=0.254
PolygonConnect PolygonConnect_FX3_GND [InNet('FX3_GND')] p7: connectstyle=Direct reliefconductorwidth=0.254 reliefentries=4 polygonreliefangle="90 Angle" airgapwidth=0.254
PolygonConnect PolygonConnect_VCC1P8 [InNet('VCC1P8')] p8: connectstyle=Direct reliefconductorwidth=0.254 reliefentries=4 polygonreliefangle="90 Angle" airgapwidth=0.254
PolygonConnect PolygonConnect_VCC1P8_LMS [InNet('VCC1P8_LMS')] p9: connectstyle=Direct reliefconductorwidth=0.254 reliefentries=4 polygonreliefangle="90 Angle" airgapwidth=0.254
PolygonConnect PolygonConnect_VCC1P8_FX3 [InNet('VCC1P8_FX3')] p10: connectstyle=Direct reliefconductorwidth=0.254 reliefentries=4 polygonreliefangle="90 Angle" airgapwidth=0.254
PolygonConnect PolygonConnect_VDIO_LMS [InNet('VDIO_LMS')] p11: connectstyle=Direct reliefconductorwidth=0.254 reliefentries=4 polygonreliefangle="90 Angle" airgapwidth=0.254
PolygonConnect PolygonConnect_VDIO_LMS_FPGA [InNet('VDIO_LMS_FPGA')] p12: connectstyle=Direct reliefconductorwidth=0.254 reliefentries=4 polygonreliefangle="90 Angle" airgapwidth=0.254
PolygonConnect PolygonConnect_VCC5P0_USB [InNetClass('VCC5P0_USB')] p13: connectstyle=Direct reliefconductorwidth=0.254 reliefentries=4 polygonreliefangle="90 Angle" airgapwidth=0.254
PolygonConnect [All] p14: connectstyle=Relief reliefconductorwidth=0.254 reliefentries=4 polygonreliefangle="90 Angle" airgapwidth=0.254
RoutingVias [All] p1: holewidth=0.2 width=0.4 viastyle="Through Hole" minholewidth=0.2 minwidth=0.31 maxholewidth=4.5 maxwidth=5
SilkToSilkClearance [All] p1: silktosilkclearance=0.1
SilkToSolderMaskClearance SilkscreenOverComponentPads [IsPad] p1: minsilkscreentomaskgap=0.1 clearancetoexposedcopper=TRUE
SolderMaskExpansion [All] p1: expansion=0.05
Width Width_ClumsyConnection [All] p1: maxlimit=7 minlimit=0.1 preferedwidth=0.2 checkconnectedcopper=TRUE
Width [All] p2: maxlimit=5 minlimit=0.1 preferedwidth=0.2
21 further rules are at their usual default settings.

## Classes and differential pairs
net class LB_CTRL: RFSW_RX_V1 RFSW_RX_V2 RFSW_TX_V1 RFSW_TX_V2 TX_LB_AT TX_LB_SH
net class BOM_VER: BOM_VER0 BOM_VER1 BOM_VER2
net class FPGA_EGPIO: FPGA_EGPIO0 FPGA_EGPIO1
net class FPGA_QSPI: FPGA_QSPI_FLASH_SS FPGA_QSPI_IO0 FPGA_QSPI_IO1 FPGA_QSPI_IO2 FPGA_QSPI_IO3 FPGA_QSPI_SCLK VCC1P8
net class VCC3P3A: VCC3P3A
net class VCC5P0_USB: VCC5P0_USB
net class VCC3P3: VCC3P3
net class VD10_FT: VD10_FT
net class AVDD_FT: AVDD_FT
net class +3.3V_DIG_LMK: +3.3V_DIG_LMK
net class LMS_I2C: LMS_I2C_SCL LMS_I2C_SDA
net class FPGA_SPI_LMS: FPGA_SPI_LMS_SS FPGA_SPI_MISO FPGA_SPI_MOSI FPGA_SPI_SCLK NetC1_1 NetIC1_D28 NetIC1_F28 NetIC1_F30
component class 09_Misc: C148 C149 C150 C151 C152 C153 C154 C155 C156 C157 C158 C159 C160 C161 C162 C163 C164 C165 C166 C167 C168 C169 C170 C171 C172 C173 C174 C175 C176 C177 C178 C179 C180 C181 C182 C183 C184 FR15 FR16 FR17 FR18 FR19 FR20 FR21 FR22 FR51 IC7 IC8 IC9 IC10 IC11 IC12 IC13 IC14 IC18 J8 J9 J10 LED1 LED2 MECH11 MECH12 MECH13 MECH14 MECH15 R57 R58 R59 R60 R61 R62 R63 R64 R65 R66 R67 R68 R69 R70 R71 R72 R73 R74 R75 R76 R77 R78 R79 R80 R81 R82 R83 R84 R85 R88 R89 R103 VT4 XO1
net class LMS_PORT2: LMS_DIQ2_D0 LMS_DIQ2_D1 LMS_DIQ2_D2 LMS_DIQ2_D3 LMS_DIQ2_D4 LMS_DIQ2_D5 LMS_DIQ2_D6 LMS_DIQ2_D7 LMS_DIQ2_D8 LMS_DIQ2_D9 LMS_DIQ2_D10 LMS_DIQ2_D11 LMS_ENABLE_IQSEL2 LMS_FCLK2 LMS_MCLK2 LMS_TXNRX2
net class LMS_PORT1: LMS_DIQ1_D0 LMS_DIQ1_D1 LMS_DIQ1_D2 LMS_DIQ1_D3 LMS_DIQ1_D4 LMS_DIQ1_D5 LMS_DIQ1_D6 LMS_DIQ1_D7 LMS_DIQ1_D8 LMS_DIQ1_D9 LMS_DIQ1_D10 LMS_DIQ1_D11 LMS_ENABLE_IQSEL1 LMS_FCLK1 LMS_MCLK1 LMS_TXNRX1
component class 04_LMS7002M_Misc: C1 C2 FL1 IC1 IC2 R1 R2 R3 R4 R5 R6 R7 R8 R9 R10 R11 R12 R13
net class CLK_PATH: NetC148_1 NetC148_2 NetC149_1 NetC182_1 NetC281_1 NetIC7_3 NetIC7_5 RXPLL_CLK TXPLL_CLK
component class 05_LMS7002M_RF: C3 C4 C5 C6 C7 C8 C9 C10 C11 C12 C13 C14 C15 C16 C17 C18 C19 C20 C21 C22 C23 C24 C25 C26 C27 C28 C29 C? ESD1 ESD2 IC3 IC4 J1 J2 L3 MECH1 MECH2 MECH3 MECH4 MECH5 MN1 MN2 MN3 MN4 MN5 MN6 MN7 MN8 MN9 MN10 MN11 MN12 MN13 MN14 MN15 MN16 MN17 MN18 MN19 MN20 MN21 MN22 MN23 MN24 MN100 MN101 MN102 MN103 R14 R15 R16 R17 R18 R19 R20 R21 R22 R23 R24 R25 T1 T2 T3 T4 VT1 VT2 VT3
component class 06_LMS7002M_Power: C30 C31 C32 C33 C34 C35 C36 C37 C38 C39 C40 C41 C42 C43 C44 C45 C46 C47 C48 C49 C50 C51 C52 C53 C54 C55 C56 C57 C58 C59 C60 C61 C62 C63 C64 C65 C66 C67 C68 C69 C70 C71 C72 C73 C74 C75 C76 C77 C78 C79 C80 C81 C82 C83 C84 C85 C86 FR1 FR2 FR3 FR4 FR5 FR6 FR7 FR8 FR9 FR10 R26 R27 R28 R29 R30 R31 R32 R33
net class TX_RF: TX1_1_A_N TX1_1_A_P TX1_1_B_N TX1_1_B_P TX2_1_A_N TX2_1_A_P TX2_1_B_N TX2_1_B_P
net class RX_RF: RX1_H_A_N RX1_H_A_P RX1_H_B_N RX1_H_B_P RX2_W_A_N RX2_W_A_P RX2_W_B_N RX2_W_B_P
net class +1.8V_DIG_LMK: +1.8V_DIG_LMK
component class 07_FPGA: C87 C88 C89 C90 C91 C92 C93 C94 C95 C96 C97 C98 C99 C100 C101 C102 C103 C104 C105 C106 C107 C108 C109 C110 C111 C112 C113 C114 C115 C116 C117 C118 C119 C120 FR11 IC5 J3 J4 J5 J6 R34 R35 R36 R37 R38 R39 R40 R41 R42 R43 R44 R45 R46 R47 R48 R49
component class 08_USB3_0_device: C121 C122 C123 C124 C125 C126 C127 C128 C129 C130 C131 C132 C133 C134 C135 C136 C137 C138 C139 C140 C141 C142 C143 C144 C145 C146 C147 ESD3 FR12 FR13 FR14 IC6 J7 MECH6 MECH7 MECH8 MECH9 MECH10 NT1 R50 R51 R52 R53 R54 R55 R56 XT1
net class FPGA_GPIO: FPGA_GPIO0 FPGA_GPIO1 FPGA_GPIO2 FPGA_GPIO3 FPGA_GPIO4 FPGA_GPIO5 FPGA_GPIO6 FPGA_GPIO7
net class FPGA_JTAG: FPGA_JTAG_TCK FPGA_JTAG_TDI FPGA_JTAG_TDO FPGA_JTAG_TMS NetJ17_7
net class FT_USB: NetJ7_7 USB_D_N USB_D_P USB_SSRX_N USB_SSRX_P USB_SSTX_N USB_SSTX_P USB_SSTXI_N USB_SSTXI_P
net class VCC1P8_LMS: VCC1P8_LMS
net class VCC3P3_CLK: VCC3P3_CLK
net class FT_FIFO: FT_BE0 FT_BE1 FT_BE2 FT_BE3 FT_CLK FT_D0 FT_D1 FT_D2 FT_D3 FT_D4 FT_D5 FT_D6 FT_D7 FT_D8 FT_D9 FT_D10 FT_D11 FT_D12 FT_D13 FT_D14 FT_D15 FT_D16 FT_D17 FT_D18 FT_D19 FT_D20 FT_D21 FT_D22 FT_D23 FT_D24 FT_D25 FT_D26 FT_D27 FT_D28 FT_D29 FT_D30 FT_D31 FT_OEN FT_RDN FT_TXEN FT_WRN
net class VDIO_LMS: VDIO_LMS
net class VDIO_LMS_FPGA: VDIO_LMS_FPGA
net class VDIO_LMS_LMK: VDIO_LMS_LMK
differential pair FT_XTAL: +FT_XTAL_P -FT_XTAL_N
differential pair USB_D: +USB_D_P -USB_D_N
differential pair USB_SSRX: +USB_SSRX_P -USB_SSRX_N
differential pair USB_SSTXI: +USB_SSTXI_P -USB_SSTXI_N
differential pair USB_SSTX: +USB_SSTX_P -USB_SSTX_N
differential pair RX1_H_A: +RX1_H_A_P -RX1_H_A_N
differential pair RX1_H_B: +RX1_H_B_P -RX1_H_B_N
differential pair RX2_W_A: +RX2_W_A_P -RX2_W_A_N
differential pair RX2_W_B: +RX2_W_B_P -RX2_W_B_N
differential pair TX1_1_A: +TX1_1_A_P -TX1_1_A_N
differential pair TX1_1_B: +TX1_1_B_P -TX1_1_B_N
differential pair TX2_1_A: +TX2_1_A_P -TX2_1_A_N
differential pair TX2_1_B: +TX2_1_B_P -TX2_1_B_N

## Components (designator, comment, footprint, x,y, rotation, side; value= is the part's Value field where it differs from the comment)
C1 "10pF, 25V" CAP0402#1 41.375,-7.06 r270 bottom
C2 "1uF, 10V" CAP0402#1 38.775,-10.46 r270 bottom
C3 "100pF, 50V" CAP0402#1 56.085,-5.31 r180 bottom
C4 "100nF, 16V" CAP0402#1 52.825,-5.81 r0 bottom
C5 "100pF, 50V" CAP0402#1 54.382,-6.253 r270 bottom
C6 "100nF, 16V" CAP0402#1 56.085,-6.31 r0 bottom
C7 "100pF, 50V" CAP0402#1 43.9,-12.135 r180 bottom
C8 "100pF, 50V" CAP0402#1 43.892,-9.218 r180 bottom
C9 "100nF, 16V" CAP0402#1 43.892,-8.218 r0 bottom
C10 "100nF, 16V" CAP0402#1 43.9,-11.11 r0 bottom
C11 "100nF, 16V" CAP0402#1 63.95,-8.235 r270 bottom
C12 "100pF, 50V" CAP0402#1 63.95,-10.285 r270 bottom
C13 "47pF, 50V" CAP0402#2 58.975,-3.435 r90 top
C14 "510pF" CAP0402#2 62.1,-6.485 r0 top
C15 "510pF" CAP0402#2 58.975,-8.985 r270 top
C16 "47pF, 50V" CAP0402#2 61.75,-3.81 r90 top
C17 "10pF, 25V" CAP0402#1 58.875,-7.66 r0 bottom
C18 "10pF, 25V" CAP0402#1 60.7,-4.91 r180 bottom
C19 "100pF, 50V" CAP0402#1 56.825,4.39 r90 bottom
C20 "100pF, 50V" CAP0402#1 57.675,12.065 r270 bottom
C21 "100nF, 16V" CAP0402#1 65.2,11.765 r180 bottom
C22 "100pF, 50V" CAP0402#1 64.225,8.365 r270 bottom
C23 "100pF, 50V" CAP0402#1 57.15,-2.76 r180 bottom
C24 "47pF, 50V" CAP0402#2 56.025,11.365 r180 top
C25 "510pF" CAP0402#2 62.025,7.94 r270 top
C26 "510pF" CAP0402#2 59.45,6.415 r270 top
C27 "47pF, 50V" CAP0402#2 62.25,11.59 r0 top
C28 "10pF, 25V" CAP0402#1 61.025,6.615 r90 bottom
C29 "10pF, 25V" CAP0402#1 59.9,10.29 r90 bottom
C30 "1uF, 6.3V" CAP0201 42.376,-6.489 r180 bottom
C31 "1nF, 10%" CAP0201 40.901,0.961 r135 bottom
C32 "1uF, 6.3V" CAP0201 43.026,-0.089 r0 bottom
C33 "1nF, 10%" CAP0201 39.625,-4.177 r90 bottom
C34 "1uF, 6.3V" CAP0201 39.77,-3.244 r180 bottom
C35 "1nF, 10%" CAP0201 38.325,0.07 r90 bottom
C36 "1uF, 6.3V" CAP0201 37.416,-0.159 r180 bottom
C37 "1nF, 10%" CAP0201 39.926,1.136 r90 bottom
C38 "1uF, 6.3V" CAP0201 39.146,1.416 r90 bottom
C39 "1nF, 10%" CAP0201 39.2,3.406 r270 bottom
C40 "1uF, 6.3V" CAP0201 40.05,3.406 r270 bottom
C41 "1uF, 6.3V" CAP0201 51.246,-4.614 r270 bottom
C42 "1uF, 6.3V" CAP0201 45.8,-6.11 r180 bottom
C43 "1uF, 6.3V" CAP0201 46.63,-5.26 r270 bottom
C44 "1uF, 6.3V" CAP0201 46.275,-3.285 r0 bottom
C45 "1uF, 6.3V" CAP0201 39.173,5.72 r315 bottom
C46 "1uF, 6.3V" CAP0201 45.476,4.406 r270 bottom
C47 "1uF, 6.3V" CAP0201 51.1,2.215 r0 bottom
C48 "1uF, 6.3V" CAP0201 51.051,-2.114 r0 bottom
C49 "1uF, 6.3V" CAP0201 40.821,5.156 r180 bottom
C50 "1uF, 6.3V" CAP0201 52.301,-3.039 r0 bottom
C51 "1uF, 6.3V" CAP0201 40.575,6.073 r90 bottom
C52 "1uF, 6.3V" CAP0201 53.944,-4.183 r270 bottom
C53 "1uF, 6.3V" CAP0201 41.925,1.936 r270 bottom
C54 "1nF, 10%" CAP0201 42.676,1.936 r270 bottom
C55 "1uF, 6.3V" CAP0201 44.875,-5.81 r270 bottom
C56 "1uF, 6.3V" CAP0201 42.176,-3.414 r180 bottom
C57 "1uF, 6.3V" CAP0201 42.251,-5.614 r270 bottom
C58 "1uF, 6.3V" CAP0201 51.43,-0.71 r180 bottom
C59 "1uF, 6.3V" CAP0201 45.125,3.213 r270 bottom
C60 "1uF, 6.3V" CAP0201 37.875,-3.312 r270 bottom
C61 "1nF, 10%" CAP0201 38.926,-3.314 r270 bottom
C62 "1uF, 6.3V" CAP0201 39.125,-1.862 r270 bottom
C63 "1nF, 10%" CAP0201 39.851,-1.871 r270 bottom
C64 "1uF, 6.3V" CAP0201 41.925,0.846 r270 bottom
C65 "1nF, 10%" CAP0201 42.676,0.836 r270 bottom
C66 "1uF, 6.3V" CAP0201 48.92,-1.66 r180 bottom
C67 "1uF, 6.3V" CAP0201 49.474,-5.265 r270 bottom
C68 "1uF, 6.3V" CAP0201 44.225,-5.735 r270 bottom
C69 "1uF, 6.3V" CAP0201 44.727,-3.109 r90 bottom
C70 "1uF, 6.3V" CAP0201 43.9,-3.455 r270 bottom
C71 "1uF, 6.3V" CAP0201 43.513,3.561 r0 bottom
C72 "1uF, 6.3V" CAP0201 41.326,6.536 r90 bottom
C73 "1uF, 6.3V" CAP0201 43.176,6.336 r90 bottom
C74 "1uF, 6.3V" CAP0201 44.12,5.218 r180 bottom
C75 "1uF, 6.3V" CAP0201 44.651,5.986 r180 bottom
C76 "1uF, 6.3V" CAP0201 49.389,3.79 r90 bottom
C77 "1uF, 6.3V" CAP0201 49.15,1.415 r90 bottom
C78 "1uF, 6.3V" CAP0201 52.05,-2.277 r90 bottom
C79 "1uF, 6.3V" CAP0201 48.195,-3.085 r0 bottom
C80 "1uF, 6.3V" CAP0201 50.001,-4.148 r315 bottom
C81 "1uF, 6.3V" CAP0201 48.151,-2.289 r180 bottom
C82 "1uF, 6.3V" CAP0201 43.15,-6.04 r270 bottom
C83 "1uF, 6.3V" CAP0201 50.388,3.357 r0 bottom
C84 "1uF, 6.3V" CAP0201 51.125,2.79 r0 bottom
C85 "1uF, 6.3V" CAP0201 49.825,1.415 r270 bottom
C86 "1uF, 6.3V" CAP0201 45.071,6.768 r180 bottom
C87 "100nF, 16V" CAP0402#1 31.45,9.015 r0 bottom
C88 "10uF, 6.3V" CAP0603#1 30.25,-6.11 r90 bottom
C89 "1uF, 6.3V" CAP0201 32.05,1.04 r0 bottom
C90 "100nF, 6.3V" CAP0201 32.05,0.365 r0 bottom
C91 "100nF, 6.3V" CAP0201 32.05,-0.285 r0 bottom
C92 "100nF, 6.3V" CAP0201 27.25,-4.135 r180 bottom
C93 "100nF, 6.3V" CAP0201 27.25,-3.435 r180 bottom
C94 "100nF, 6.3V" CAP0201 32.05,1.665 r0 bottom
C95 "10uF, 6.3V" CAP0603#1 32.05,-4.86 r90 bottom
C96 "1uF, 6.3V" CAP0201 27.25,-2.66 r180 bottom
C97 "100nF, 6.3V" CAP0201 25.15,-2.86 r270 bottom
C98 "100nF, 6.3V" CAP0201 24.6,-2.21 r90 bottom
C99 "100nF, 6.3V" CAP0201 23.45,-3.535 r270 bottom
C100 "100nF, 6.3V" CAP0201 32.05,2.315 r0 bottom
C101 "100nF, 6.3V" CAP0201 21.825,-6.935 r180 top
C102 "10uF, 6.3V" CAP0603#1 22.55,6.04 r0 bottom
C103 "1uF, 6.3V" CAP0201 30.275,4.365 r90 bottom
C104 "100nF, 6.3V" CAP0201 20.925,2.24 r180 bottom
C105 "100nF, 6.3V" CAP0201 20.95,2.815 r180 bottom
C106 "100nF, 6.3V" CAP0201 20.92,3.65 r180 bottom
C107 "100nF, 6.3V" CAP0201 27.65,5.865 r90 bottom
C108 "10uF, 6.3V" CAP0603#1 22.05,-5.085 r0 bottom
C109 "1uF, 6.3V" CAP0201 25.2,-4.535 r270 bottom
C110 "100nF, 6.3V" CAP0201 24.525,-4.535 r270 bottom
C111 "100nF, 6.3V" CAP0201 25.85,-4.535 r270 bottom
C112 "10uF, 6.3V" CAP0603#1 31.25,4.4 r270 bottom
C113 "1uF, 6.3V" CAP0201 25.25,-1.885 r270 bottom
C114 "100nF, 6.3V" CAP0201 26.86,5.861 r90 bottom
C115 "100nF, 6.3V" CAP0201 26.025,-1.885 r270 bottom
C116 "100nF, 6.3V" CAP0201 20.925,0.115 r180 bottom
C117 "100nF, 6.3V" CAP0201 25.295,5.886 r90 bottom
C118 "100nF, 6.3V" CAP0201 26.04,5.861 r90 bottom
C119 "100nF, 6.3V" CAP0201 26.75,-1.91 r270 bottom
C120 "100nF, 6.3V" CAP0201 20.925,0.965 r180 bottom
C121 "100nF, 6.3V" CAP0201 9.45,-0.685 r0 top
C122 "100nF, 6.3V" CAP0201 9.45,-1.315 r0 top
C123 "100nF, 16V" CAP0402#1 7.725,-5.86 r270 bottom
C124 "10pF, 5%" CAP0402#2 8.525,4.765 r270 top
C125 "100nF, 16V" CAP0402#1 1.75,0.515 r0 bottom
C126 "10pF, 5%" CAP0402#2 8.025,6.765 r90 top
C127 "100nF, 16V" CAP0402#1 4.375,7.64 r180 bottom
C128 "10uF, 6.3V" CAP0603#1 14.45,-5.96 r0 bottom
C129 "1uF, 6.3V" CAP0201 18.875,-3.9 r90 bottom
C130 "100nF, 6.3V" CAP0201 14,3.34 r0 bottom
C131 "1uF, 6.3V" CAP0201 14.9,-4.65 r0 bottom
C132 "100nF, 6.3V" CAP0201 12.875,3.34 r180 bottom
C133 "1uF, 6.3V" CAP0201 15.95,-4.65 r180 bottom
C134 "100nF, 6.3V" CAP0201 19.625,0.925 r90 bottom
C135 "1uF, 6.3V" CAP0201 19.675,-0.125 r90 bottom
C136 "100nF, 6.3V" CAP0201 18.2,-3.2 r180 bottom
C137 "10uF, 6.3V" CAP0603#1 10.675,-3.85 r270 bottom
C138 "1uF, 6.3V" CAP0201 13.9,-3.175 r0 bottom
C139 "100nF, 6.3V" CAP0201 18.225,4.55 r0 bottom
C140 "10nF, 16V" CAP0402#1 15.55,-3.175 r0 bottom
C141 "100nF, 6.3V" CAP0201 11.865,-0.4 r0 bottom
C142 "10nF, 16V" CAP0402#1 16.575,4.55 r180 bottom
C143 "100nF, 6.3V" CAP0201 11.865,-1.6 r0 bottom
C144 "10nF, 16V" CAP0402#1 10.975,-5.91 r0 bottom
C145 "10uF, 6.3V" CAP0603#1 16.975,3.015 r0 bottom
C146 "1uF, 6.3V" CAP0201 11.15,-8.36 r90 bottom
C147 "100nF, 16V" CAP0402#1 12.025,-8.41 r270 bottom
C148 "100nF, 16V" CAP0402#1 22.7,7.615 r270 bottom
C149 "100nF, 16V" CAP0402#1 19.675,12.34 r0 bottom
C150 "100nF, 16V" CAP0402#1 40.075,8.865 r270 bottom
C151 "18nF, 16V" CAP0402#1 25.6,9.415 r90 bottom
C152 "47pF" CAP0402#2 24.675,10.64 r270 top
C153 "1uF, 10V" CAP0402#1 23.725,11.615 r270 bottom
C154 "47pF" CAP0402#2 24.7,7.765 r90 top
C155 "100nF, 16V" CAP0402#1 24.65,11.615 r270 bottom
C156 "100nF, 16V" CAP0402#2 16.725,11.915 r0 top
C157 "1uF, 10V" CAP0402#2 22.575,10.425 r270 top
C158 "100nF, 16V" CAP0402#2 20.825,10.04 r0 top
C159 "100pF, 50V" CAP0402#2 21,8.75 r0 top
C160 "100pF, 50V" CAP0402#2 19.3,7.84 r0 top
C161 "100nF, 16V" CAP0402#1 15.675,12.19 r180 bottom
C162 "100nF, 16V" CAP0402#1 33.925,4.715 r270 bottom
C163 "100nF, 16V" CAP0402#1 9.6,9.34 r180 bottom
C164 "1uF, 10V" CAP0402#2 16.625,7.19 r0 top
C165 "100nF, 16V" CAP0402#1 15.675,10.09 r0 bottom
C166 "100pF, 50V" CAP0402#2 16.675,9.89 r0 top
C167 "100pF, 50V" CAP0402#2 16.675,8.89 r0 top
C168 "1uF, 10V" CAP0402#2 20.95,6.84 r90 top
C169 "100nF, 16V" CAP0402#2 17.85,10.915 r0 top
C170 "100pF, 50V" CAP0402#2 19.3,6.94 r0 top
C171 "100pF, 50V" CAP0402#2 20.775,12.29 r180 top
C172 "100nF, 16V" CAP0402#1 7.45,-11.76 r90 bottom
C173 "1uF, 10V" CAP0402#1 21.325,-11.46 r90 bottom
C174 "100nF, 16V" CAP0402#1 22.325,-11.46 r270 bottom
C175 "10uF, 6.3V" CAP0603#1 30.75,-9.81 r0 bottom
C176 "10uF, 16V" CAP0603#1 25.9,-11.635 r180 bottom
C177 "10uF, 16V" CAP0603#1 16.589,-11.645 r180 bottom
C178 "4.7uF, 6.3V" CAP0402#2 13.25,-11.36 r0 top
C179 "4.7uF, 6.3V" CAP0402#2 8.5,-6.61 r270 top
C180 "10uF, 6.3V" CAP0603#2 8.3,-11.185 r90 top
C181 "22uF, 10V" CAP0603#1 27.161,-10.42 r0 bottom
C182 "22uF, 10V" CAP0603#1 17.85,-10.38 r0 bottom
C183 "100pF, 50V" CAP0402#1 12.5,-6.36 r270 bottom
C184 "10uF, 6.3V" CAP0603#1 13,8.065 r90 bottom
ESD1 "ESD8472" ESD8472_X3DFN2 62.85,-7.485 r270 top
ESD2 "ESD8472" ESD8472_X3DFN2 62.85,6.965 r270 top
ESD3 "ESD7016" ESD7016 8.08,-1 r0 top
FL1 "Fiducial" Fiducial_local 34.6,3.915 r0 top
FR1 "600R, 0.27A" RES0201 52.131,-4.334 r0 bottom
FR2 "600R, 0.27A" RES0201 51.424,-1.376 r180 bottom
FR3 "600R, 0.27A" RES0201 51.1,1.565 r180 bottom
FR4 "600R, 0.27A" RES0201 45.826,6.111 r90 bottom
FR5 "600R, 0.27A" RES0201 38.8,6.798 r90 bottom
FR6 "600R, 0.27A" RES0201 46.275,-3.785 r0 bottom
FR7 "600R, 0.27A" RES0201 46.905,-4.51 r0 bottom
FR8 "600R, 0.27A" RES0201 47.175,-5.685 r90 bottom
FR9 "600R, 0.27A" RES0201 52.305,-3.757 r180 bottom
FR10 "600R, 0.27A" RES0201 41.876,5.436 r90 bottom
FR11 "220R, 0.9A" RES0402#1 22.475,-9.01 r90 top
FR12 "600R, 2A" RES0805#1 4.675,-3.035 r270 bottom
FR13 "220R, 0.9A" RES0402#2 1.752,-0.515 r180 bottom
FR14 "220R, 0.9A" RES0402#2 10.225,-7.435 r270 bottom
FR15 "600R, 0.27A" RES0201 24.525,10.265 r0 bottom
FR16 "600R, 0.27A" RES0201 21.325,11.075 r270 top
FR17 "600R, 0.27A" RES0201 11.25,9.365 r180 bottom
FR18 "600R, 0.27A" RES0201 15.875,9.19 r0 bottom
FR19 "600R, 0.27A" RES0201 22.525,6.49 r180 top
FR20 "600R, 2A" RES0805#1 30.775,-11.31 r0 bottom
FR21 "220R, 0.9A" RES0402#1 8.475,-8.71 r270 top
FR22 "220R, 0.9A" RES0402#1 20.25,5.24 r0 top
IC1 "LMS7002M" LMS7002M_v4 45.391,-0.044 r180 top locked
IC2 "M24128S" M24128S 37.449,-9.746 r90 bottom
IC3 "SKY13411-374LF" SKY13411-374LF 59.475,-6.135 r90 top
IC4 "SKY13411-374LF" SKY13411-374LF 59.85,9.69 r90 top
IC5 "10M16SAU169C8G" 10M16SAU169C8G 26.85,0 r90 top locked
IC6 "FT601Q" FT601Q 15.025,0 r270 top locked
IC7 "LMK00105" LMK00105SQ 19.4,9 r180 bottom
IC8 "LM75" HWSON8_LM75 36,7.24 r270 bottom
IC9 "DAC5311IDCKR" AD5601_SOT23-6 10.875,10.965 r180 bottom
IC10 "M24128S" M24128S 38.775,8.69 r180 bottom
IC11 "W25Q40EWUXIE" W25Q40EWUXIE_8-USON 21.325,-8.41 r270 bottom
IC12 "LXDC55K" LXDC55K 26.25,-9.685 r90 top
IC13 "LXDC55K" LXDC55K 16.939,-9.695 r90 top
IC14 "LD39100PUR" LD39100PUR 12.625,-8.96 r180 top
J1 "SMA board edge" SMA_CONNECTOR_BOARD_EDGE_SM 66.845,-7.248 r90 top locked
J2 "SMA board edge" SMA_CONNECTOR_BOARD_EDGE_SM 66.845,7.252 r90 top locked
J3 "FPGA JTAG (board edge)" HEADER7X1_TH_V2 15.725,14.89 r0 top
J4 "FPGA JTAG" SWD_10_pin 12.225,9.05 r270 top
J5 "FPGA GPIO" SWD_10_pin 28.65,9.1 r270 top
J6 "FPGA EGPIO (board edge)" Header5x1_TH_v2 13.225,-14.89 r0 top
J7 "USB3.0_MALE" USB3A_SM 3.65,0 r90 top locked
J8 "U.FL/MMCX" MMCX_UFL_conn_u 40.55,12.615 r0 bottom
J9 "U.FL/MMCX" MMCX_UFL_conn_u 35.95,12.615 r0 bottom
J10 "FAN" HDR_1x2_v2 4.925,-13.185 r0 top
LED1 "LED_RG_SMD" LED-2x0603 65.425,-0.01 r180 top
LED2 "LED_RG_angle" LED_RG_RIGHT_ANGLE_v2 67.55,0 r270 bottom
MECH1 "RFI Shield clip" RFI_SHIELD_CLPS_MINI 55.75,-13.26 r180 top
MECH2 "RFI Shield clip" RFI_SHIELD_CLPS_MINI 39.25,-13.26 r180 top
MECH3 "RFI Shield clip" RFI_SHIELD_CLPS_MINI 55.75,13.24 r180 top
MECH4 "RFI Shield clip" RFI_SHIELD_CLPS_MINI 39.25,13.24 r180 top
MECH5 "RFI Shield" WURTHELECTRONIC_RF_SHIELD 34.15,-13.41 r0 top
MECH6 "RFI Shield clip" RFI_SHIELD_CLPS_MINI 11.475,-13.26 r180 top
MECH7 "RFI Shield" WURTHELECTRONIC_RF_SHIELD 6.4,-13.41 r0 top
MECH8 "RFI Shield clip" RFI_SHIELD_CLPS_MINI 27.975,-13.26 r180 top
MECH9 "RFI Shield clip" RFI_SHIELD_CLPS_MINI 11.475,13.24 r180 top
MECH10 "RFI Shield clip" RFI_SHIELD_CLPS_MINI 27.975,13.24 r180 top
MECH11 "RFI Shield clip" RFI_SHIELD_CLPS_MINI 11.475,-13.26 r180 bottom
MECH12 "RFI Shield clip" RFI_SHIELD_CLPS_MINI 27.975,-13.26 r180 bottom
MECH13 "RFI Shield clip" RFI_SHIELD_CLPS_MINI 11.475,13.24 r180 bottom
MECH14 "RFI Shield clip" RFI_SHIELD_CLPS_MINI 27.975,13.24 r180 bottom
MECH15 "RFI Shield" WURTHELECTRONIC_RF_SHIELD 33.2,-13.41 r180 bottom
MN1 "8.2nH, 5%" RES0402#1 54.493,-5.808 r180 top
MN2 "8.2nH, 5%" RES0402#1 56.493,-5.808 r0 top
MN3 "0.8pF" CAP0402#2 56,-3.2 r90 top
MN4 "1pF" CAP0402#2 55.5,-4.75 r0 top
MN5 "0.5pF" CAP0402#2 55.5,-1.65 r180 top
MN6 "0.8pF" CAP0402#2 55,-3.2 r270 top
MN7 "100uH" RES0805#2 46.412,-11.618 r180 top
MN8 "100uH" RES0805#2 46.412,-8.718 r180 top
MN9 "0R" RES0402#1 48.435,-11.17 r270 top
MN10 "0R" RES0402#1 48.435,-9.17 r90 top
MN11 "100nF, 16V" CAP0402#2 51.035,-9.67 r180 top
MN12 "1pF" CAP0402#2 49.485,-10.17 r270 top
MN13 "2pF" CAP0402#2 52.585,-10.17 r90 top
MN14 "100nF, 16V" CAP0402#2 51.035,-10.67 r0 top
MN15 "2pF" CAP0402#2 44.675,9.99 r180 top
MN16 "0.5pF" CAP0402#2 46.275,10.49 r270 top
MN17 "1pF" CAP0402#2 43.125,10.49 r270 top
MN18 "2pF" CAP0402#2 44.675,10.99 r180 top
MN19 "510pF" CAP0402#2 52.275,6.865 r180 top
MN20 "8.2nH, 5%" RES0402#1 53.875,7.365 r270 top
MN21 "1.2pF" CAP0402#2 50.732,7.373 r270 top
MN22 "510pF" CAP0402#2 52.275,7.865 r180 top
MN23 "100uH" RES0805_0603 63.95,-8.16 r270 top
MN24 "100uH" RES0805_0603 63.95,8.14 r90 top
NT1 "NetTie" NetTie_Wide2 8,-7.31 r270 top net-tie
R1 "10k, 1%" RES0402#2 36.3,2.64 r90 bottom
R2 "10k, 1%" RES0402#1 30.55,-6.135 r0 top
R3 "10k, 1%" RES0402#2 37.3,-2.11 r0 bottom
R4 "10k, 1%" RES0402#2 34.625,-1.16 r90 bottom
R5 "10k, 1%" RES0402#1 35.775,-0.81 r90 top
R6 "49.9R, 1%" RES0402#2 39.751,-7.814 r180 bottom
R7 "49.9R, 1%" RES0402#2 38.85,-5.682 r180 bottom
R8 "49.9R, 1%" RES0402#2 39.65,-6.782 r180 bottom
R9 "49.9R, 1%" RES0402#2 36.6,-6.257 r180 bottom
R10 "10k, 1%" RES0402#2 34.425,1.865 r90 bottom
R11 "10k, 1%" RES0402#2 45.325,-1.607 r135 bottom
R12 "2k2, 1%" RES0402#2 35.55,-10.26 r0 bottom
R13 "2k2, 1%" RES0402#2 39.1,-8.86 r180 bottom
R14 "0R" RES0402#2 62.3,-8.71 r0 bottom
R15 "0R" RES0402#2 62.3,-9.807 r0 bottom
R16 "560R, 1%" RES0402#2 62.787,5.102 r180 bottom
R17 "100R, 1%" RES0402#2 58.375,3.89 r180 bottom
R18 "2.49k, 1%" RES0402#2 63.112,3.502 r90 bottom
R19 "1k, 1%" RES0402#2 61.512,0.577 r180 bottom
R20 "0R" RES0402#2 64.35,13.315 r270 bottom
R21 "0R" RES0402#2 65.45,13.315 r270 bottom
R22 "100R, 1%" RES0402#2 59.25,12.565 r0 bottom
R23 "49.9R, 1%" RES0402#2 62.262,-0.523 r180 bottom
R24 "49.9R, 1%" RES0402#2 63.825,6.215 r180 bottom
R25 "100R, 1%" RES0402#2 58.225,-3.81 r180 bottom
R26 "0R" RES0201 42.606,-7.309 r270 bottom
R27 "0R" RES0402#2 37.826,3.686 r0 bottom
R28 "0R" RES0402#2 37.822,2.59 r0 bottom
R29 "0R" RES0402#2 37.301,-1.064 r0 bottom
R30 "0R" RES0402#2 37.8,-4.407 r0 bottom
R31 "0R" RES0402#2 41.976,-0.714 r90 bottom
R32 "10R" RES0201 53.046,-4.198 r270 bottom
R33 "10R" RES0201 39.801,6.811 r270 bottom
R34 "10k, 1%" RES0402#2 9.925,8.065 r0 bottom
R35 "10k, 1%" RES0402#2 4.375,9.79 r0 bottom
R36 "10k, 1%" RES0402#2 11.7,7.565 r90 bottom
R37 "10k, 1%" RES0402#2 20.975,-3.41 r90 bottom
R38 "10k, 1%" RES0402#2 4.375,10.89 r0 bottom
R39 "1k, 1%" RES0402#2 8.025,10.365 r270 bottom
R40 "0R" RES0402#2 31.1,10.49 r180 bottom
R41 "0R" RES0402#2 31.094,11.606 r180 bottom
R42 "0R" RES0402#1 31.625,-11.76 r180 top
R43 "0R" RES0402#1 31.627,-10.665 r180 top
R44 "0R" RES0402#1 31.625,-9.56 r180 top
R45 "10k, 1%" RES0402#2 18.175,1.29 r90 bottom
R46 "10k, 1%" RES0402#2 20.125,5.79 r0 bottom
R47 "10k, 1%" RES0402#2 19.575,4.24 r90 bottom
R48 "10k, 1%" RES0402#2 19.525,-2.01 r90 bottom
R49 "10k, 1%" RES0402#2 20.875,-1.36 r90 bottom
R50 "4K7, 1%" RES0402#2 8.775,-4.86 r270 bottom
R51 "10k, 1%" RES0402#2 8.775,-2.76 r270 bottom
R52 "0R" RES0402#2 3.775,1.415 r270 bottom
R53 "10k, 1%" RES0402#2 14.475,4.49 r180 bottom
R54 "10k, 1%" RES0402#2 12.45,4.49 r0 bottom
R55 "10k, 1%" RES0402#2 4.375,8.69 r180 bottom
R56 "1k6, 1%" RES0402#2 10.1,0.79 r0 bottom
R57 "0R" RES0402#1 19.95,10.99 r180 top
R58 "10k, 1%" RES0402#2 37.075,9.69 r0 bottom
R59 "0R" RES0402#2 25.075,7.315 r180 bottom
R60 "22R" RES0402#2 23.375,9.59 r270 bottom
R61 "0R" RES0402#1 23.625,9.84 r270 top
R62 "0R" RES0402#2 24.588,7.818 r270 bottom
R63 "49.9R, 1%" RES0402#2 22.125,12.34 r180 bottom
R64 "1k, 1%" RES0402#2 33.9,6.715 r90 bottom
R65 "0R" RES0402#1 23.1,8.265 r180 top
R66 "1k, 1%" RES0402#2 34.975,9.69 r0 bottom
R67 "3k, 1%" RES0402#2 4.925,12.49 r270 bottom
R68 "10k, 1%" RES0402#2 15.675,11.14 r0 bottom
R69 "0R" RES0402#2 12.9,-11.935 r180 bottom
R70 "100R, 1%" RES0402#2 63.775,-1.635 r180 bottom
R71 "0R" RES0402#2 11.3,-10.835 r180 bottom
R72 "100R, 1%" RES0402#2 63.225,1.14 r270 bottom
R73 "100R, 1%" RES0402#2 64.375,0.515 r90 bottom
R74 "0R" RES0402#2 7.95,-7.61 r0 bottom
R75 "100R, 1%" RES0402#2 63.775,-2.735 r180 bottom
R76 "10k, 1%" RES0402#2 27.45,-8.585 r180 bottom
R77 "0R" RES0402#1 12.3,-6.185 r180 top
R78 "10k, 1%" RES0402#2 18.164,-8.595 r180 bottom
R79 "0R" RES0402#1 10.075,-8.21 r90 top
R80 "10k, 1%" RES0402#1 10.475,-10.31 r90 top
R81 "4K7, 1%" RES0402#1 9.975,-11.91 r180 top
R82 "0R" RES0402#2 16.95,-6.31 r0 bottom
R83 "3.83k, 1%" RES0402#2 27.45,-7.485 r0 bottom
R84 "0R" RES0402#2 15.3,-7.985 r90 bottom
R85 "576R, 1%" RES0402#2 18.139,-7.495 r0 bottom
T1 "JA4220-AL_" JA4220-AL_ 55.5,1.24 r180 top
T2 "JA4220-AL_" JA4220-AL_ 55.475,-10.17 r90 top
T3 "JA4220-AL_" JA4220-AL_ 49.165,10.49 r90 top
T4 "JA4220-AL_" JA4220-AL_ 56.69,7.365 r90 top
VT1 "RF MOSFET" BF1105R_SOT143R4 61.012,2.952 r270 bottom
VT2 "RF MOSFET" BF1105R_SOT143R4 62.288,11.677 r180 bottom
VT3 "RF MOSFET" BF1105R_SOT143R4 60.738,-2.872 r270 bottom
VT4 "NDS331N" SOT23-3 8.55,-10.21 r180 bottom
XO1 "RTX5032A, 40MHz, w VC, w Filter" RAKON_RTX5032A 28,9.19 r270 bottom
XT1 "30MHz" CRYSTAL_4-LCC 9.025,5.765 r0 bottom

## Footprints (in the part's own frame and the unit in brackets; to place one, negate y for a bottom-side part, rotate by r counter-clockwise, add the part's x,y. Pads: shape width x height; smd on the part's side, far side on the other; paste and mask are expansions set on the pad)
10M16SAU169C8G [mm] "BGA, 169-Leads, Body 11,00x11,00mmx1,55mm, Pitch 0,80mm"
  oval 0.5x0.47 smd mask+0.02: A1(-4.8,4.8) G1(-4.8,0) H1(-4.8,-0.8)
  round 0.5 smd mask+0.02: A2(-4,4.8) A3(-3.2,4.8) A4(-2.4,4.8) A5(-1.6,4.8) A6(-0.8,4.8) A7(0,4.8) A8(0.8,4.8) A9(1.6,4.8) A10(2.4,4.8) A11(3.2,4.8) A12(4,4.8) A13(4.8,4.8) B3(-3.2,4) B4(-2.4,4) B5(-1.6,4) B6(-0.8,4) B7(0,4) B8(0.8,4) B9(1.6,4) B10(2.4,4) B11(3.2,4) B12(4,4) B13(4.8,4) C1(-4.8,3.2) C2(-4,3.2) C3(-3.2,3.2) C4(-2.4,3.2) C5(-1.6,3.2) C6(-0.8,3.2) C7(0,3.2) C8(0.8,3.2) C9(1.6,3.2) C10(2.4,3.2) C11(3.2,3.2) C12(4,3.2) C13(4.8,3.2) D1(-4.8,2.4) D2(-4,2.4) D3(-3.2,2.4) D4(-2.4,2.4) D5(-1.6,2.4) D6(-0.8,2.4) D7(0,2.4) D8(0.8,2.4) D9(1.6,2.4) D10(2.4,2.4) D11(3.2,2.4) D12(4,2.4) D13(4.8,2.4) E1(-4.8,1.6) E2(-4,1.6) E3(-3.2,1.6) E4(-2.4,1.6) E5(-1.6,1.6) E6(-0.8,1.6) E7(0,1.6) E8(0.8,1.6) E9(1.6,1.6) E10(2.4,1.6) E11(3.2,1.6) E12(4,1.6) E13(4.8,1.6) F1(-4.8,0.8) F2(-4,0.8) F3(-3.2,0.8) F4(-2.4,0.8) F5(-1.6,0.8) F6(-0.8,0.8) F7(0,0.8) F8(0.8,0.8) F9(1.6,0.8) F10(2.4,0.8) F11(3.2,0.8) F12(4,0.8) F13(4.8,0.8) G2(-4,0) G3(-3.2,0) G4(-2.4,0) G5(-1.6,0) G6(-0.8,0) G7(0,0) G8(0.8,0) G9(1.6,0) G10(2.4,0) G11(3.2,0) G12(4,0) G13(4.8,0) H2(-4,-0.8) H3(-3.2,-0.8) H4(-2.4,-0.8) H5(-1.6,-0.8) H6(-0.8,-0.8) H7(0,-0.8) H8(0.8,-0.8) H9(1.6,-0.8) H10(2.4,-0.8) H11(3.2,-0.8) H12(4,-0.8) H13(4.8,-0.8) J1(-4.8,-1.6) J2(-4,-1.6) J3(-3.2,-1.6) J4(-2.4,-1.6) J5(-1.6,-1.6) J6(-0.8,-1.6) J7(0,-1.6) J8(0.8,-1.6) J9(1.6,-1.6) J10(2.4,-1.6) J11(3.2,-1.6) J12(4,-1.6) J13(4.8,-1.6) K1(-4.8,-2.4) K2(-4,-2.4) K3(-3.2,-2.4) K4(-2.4,-2.4) K5(-1.6,-2.4) K6(-0.8,-2.4) K7(0,-2.4) K8(0.8,-2.4) K9(1.6,-2.4) K10(2.4,-2.4) K11(3.2,-2.4) K12(4,-2.4) K13(4.8,-2.4) L1(-4.8,-3.2) L2(-4,-3.2) L3(-3.2,-3.2) L4(-2.4,-3.2) L5(-1.6,-3.2) L6(-0.8,-3.2) L7(0,-3.2) L8(0.8,-3.2) L9(1.6,-3.2) L10(2.4,-3.2) L11(3.2,-3.2) L12(4,-3.2) L13(4.8,-3.2) M1(-4.8,-4) M2(-4,-4) M3(-3.2,-4) M4(-2.4,-4) M5(-1.6,-4) M6(-0.8,-4) M7(0,-4) M8(0.8,-4) M9(1.6,-4) M10(2.4,-4) M11(3.2,-4) M12(4,-4) M13(4.8,-4) N1(-4.8,-4.8) N2(-4,-4.8) N3(-3.2,-4.8) N4(-2.4,-4.8) N5(-1.6,-4.8) N6(-0.8,-4.8) N7(0,-4.8) N8(0.8,-4.8) N9(1.6,-4.8) N10(2.4,-4.8) N11(3.2,-4.8) N12(4,-4.8) N13(4.8,-4.8)
  round 0.47 smd mask+0.02: B1(-4.8,4)
  oval 0.45x0.5 smd mask+0.02: B2(-4,4)
  silkscreen extent -6.37,-5.6 5.6,5.6, body extent -5.5,-5.5 5.5,5.5, height 1.65
AD5601_SOT23-6 [mm] "SOT23, 6-Leads, Body 2x1.3mm, Pitch 0.65mm, Lead Span 2.1mm, IPC Medium Density"
  rect 0.85x0.4 smd mask+0.05: 1(-0.95,0.65) 2(-0.95,0) 3(-0.95,-0.65) 4(0.95,-0.65) 5(0.95,0) 6(0.95,0.65)
  silkscreen extent -0.95,-1.1 0.15,1.1, body extent -1.05,-1 1.05,1, height 0.43
BF1105R_SOT143R4 [mm] "RF MOSFET Transistors Trans MOSFET N-CH 7V 0.03A 4pin(3+Tab). SOT-143R-4 package"
  rect 1x0.7 smd: 1(0.763,-0.987)
  rect 0.7x0.7 smd: 2(-0.962,-0.987) 3(-0.937,0.988) 4(0.963,0.988)
  silkscreen extent -1.5,-1.73 1.53,0.63, body extent -1.44,-1.26 1.46,1.24, height 0.95
CAP0201 [mm]
  rect 0.3x0.35 smd: 1(-0.28,0) 2(0.28,0)
  silkscreen extent -0.2,-0.33 0.2,0.33, body extent -0.3,-0.15 0.3,0.15, height 0.25
CAP0402#1 [mm] "Chip Capacitor, Body 1.0x0.5mm, 0402, IPC Medium Density"
  round 0.2 on Mech14: 0(0,0)
  rrect20% 0.6x0.5 smd: 1(-0.5,0) 2(0.5,0)
  Top pour cut-out: -0.2,0.35 0.2,0.35 0.2,-0.35 -0.2,-0.35
  silkscreen extent -1.05,-0.5 1.05,0.5, body extent -0.52,-0.27 0.53,0.28, height 0.55
CAP0402#2 [mm] "Chip Capacitor, Body 1.0x0.5mm, 0402, IPC Medium Density"
  round 0.2 on Mech15: 0(0,0)
  rrect20% 0.6x0.5 smd: 1(-0.5,0) 2(0.5,0)
  Top pour cut-out: -0.2,0.35 0.2,0.35 0.2,-0.35 -0.2,-0.35
  silkscreen extent -1.05,-0.5 1.05,0.5, body extent -0.52,-0.27 0.53,0.28, height 0.55
CAP0603#1 [mm] "Chip Capacitor, Body 1.6x0.8mm, 0603, IPC Medium Density"
  round 0.254 on Mech14: 0(0,0)
  rrect25% 0.9x1 smd: 1(-0.85,0) 2(0.85,0)
  Top pour cut-out: -0.4,0.6 0.4,0.6 0.4,-0.6 -0.4,-0.6
  silkscreen extent -0.18,-0.48 0.18,0.48, body extent -0.85,-0.45 0.85,0.45, height 0.89
CAP0603#2 [mm] "Chip Capacitor, Body 1.6x0.8mm, 0603, IPC Medium Density"
  round 0.254 on Mech15: 0(0,0)
  rrect25% 0.9x1 smd: 1(-0.85,0) 2(0.85,0)
  Top pour cut-out: -0.4,0.6 0.4,0.6 0.4,-0.6 -0.4,-0.6
  silkscreen extent -0.18,-0.48 0.18,0.48, body extent -0.85,-0.45 0.85,0.45, height 0.89
CRYSTAL_4-LCC [mm] "SMD Crystal 4-lead leadless package"
  round 0.508 on Mech14: 0(0,0)
  rrect25% 1.4x1.2 smd: 1(-1.1,-0.85) 2(1.1,-0.85) 3(1.1,0.85) 4(-1.1,0.85)
  silkscreen extent -2.3,-1.6 2,1.6, body extent -1.65,-1.3 1.65,1.3, height 0.8
ESD7016 [mm]
  rect 0.5x0.25 smd mask+0.05: 1(-0.287,1.4)
  rect 0.4x0.25 smd mask+0.05: 2(-0.337,1) 3(-0.337,0.6) 4(-0.337,0.2) 5(-0.337,-0.2) 6(-0.337,-0.6) 7(-0.337,-1) 8(-0.337,-1.4)
  rect 0.65x0.45 smd mask+0.05: 9(0.337,0.58) 10(0.337,-0.58)
  silkscreen extent -0.56,-1.65 0.69,1.65
ESD8472_X3DFN2 [mm]
  rect 0.31x0.3 smd paste-1 mask+0.05: 1(-0.225,0) 2(0.225,0)
  silkscreen extent -0.2,-0.33 0.2,0.33
Fiducial_local [mm]
  round 1 smd paste-1 mask+0.5: 1(0,0)
  Top pour cut-out: -1.05,0 -0.97,-0.402 -0.742,-0.742 -0.402,-0.97 0,-1.05 0,-1.05 0.402,-0.97 0.742,-0.742 0.97,-0.402 1.05,0 1.05,0 0.97,0.402 0.742,0.742 0.402,0.97 0,1.05 0,1.05 -0.402,0.97 -0.742,0.742 -0.97,0.402 -1.05,0
FT601Q [mm] "QFN, 76-Leads, Body 9,05x9,05mm, Pitch 0,40mm, Thermal Pad 5,55x5,55mm, IPC High Density"
  rect 0.9x0.2 smd mask+0.05: 1(-4.5,3.6) 2(-4.5,3.2) 3(-4.5,2.8) 4(-4.5,2.4) 5(-4.5,2) 6(-4.5,1.6) 7(-4.5,1.2) 8(-4.5,0.8) 9(-4.5,0.4) 10(-4.5,0) 11(-4.5,-0.4) 12(-4.5,-0.8) 13(-4.5,-1.2) 14(-4.5,-1.6) 15(-4.5,-2) 16(-4.5,-2.4) 17(-4.5,-2.8) 18(-4.5,-3.2) 19(-4.5,-3.6) 39(4.5,-3.6) 40(4.5,-3.2) 41(4.5,-2.8) 42(4.5,-2.4) 43(4.5,-2) 44(4.5,-1.6) 45(4.5,-1.2) 46(4.5,-0.8) 47(4.5,-0.4) 48(4.5,0) 49(4.5,0.4) 50(4.5,0.8) 51(4.5,1.2) 52(4.5,1.6) 53(4.5,2) 54(4.5,2.4) 55(4.5,2.8) 56(4.5,3.2) 57(4.5,3.6)
  rect 0.2x0.9 smd mask+0.05: 20(-3.6,-4.5) 21(-3.2,-4.5) 22(-2.8,-4.5) 23(-2.4,-4.5) 24(-2,-4.5) 25(-1.6,-4.5) 26(-1.2,-4.5) 27(-0.8,-4.5) 28(-0.4,-4.5) 29(0,-4.5) 30(0.4,-4.5) 31(0.8,-4.5) 32(1.2,-4.5) 33(1.6,-4.5) 34(2,-4.5) 35(2.4,-4.5) 36(2.8,-4.5) 37(3.2,-4.5) 38(3.6,-4.5) 58(3.6,4.5) 59(3.2,4.5) 60(2.8,4.5) 61(2.4,4.5) 62(2,4.5) 63(1.6,4.5) 64(1.2,4.5) 65(0.8,4.5) 66(0.4,4.5) 67(0,4.5) 68(-0.4,4.5) 69(-0.8,4.5) 70(-1.2,4.5) 71(-1.6,4.5) 72(-2,4.5) 73(-2.4,4.5) 74(-2.8,4.5) 75(-3.2,4.5) 76(-3.6,4.5)
  rect 5.55x5.55 smd: 77(0,0)
  silkscreen extent -5.3,-4.7 4.7,4.7, body extent -4.56,-4.56 4.56,4.56, height 1
HDR_1x2_v2 [mm]
  rrect25% 1.524x1.524 hole 1: 1(0,1.27)
  round 1.6 hole 1: 2(0,-1.27)
  silkscreen extent -1.17,-2.07 1.17,2.05
Header5x1_TH_v2 [mm]
  rrect50% 1.8x1.3 hole 1: 1(-5.086,0)
  oval 1.8x1.3 hole 1: 2(-2.543,0) 3(0,0) 4(2.543,0) 5(5.086,0)
  silkscreen extent -6.46,-0.8 6.46,0.8
HEADER7X1_TH_V2 [mm]
  rrect50% 1.8x1.3 hole 1: 1(-7.629,0)
  oval 1.8x1.3 hole 1: 2(-5.086,0) 3(-2.543,0) 4(0,0) 5(2.543,0) 6(5.086,0) 7(7.629,0)
  silkscreen extent -9,-0.8 9,0.8
HWSON8_LM75 [mm]
  rect 0.625x0.25 smd: 1(-1.4,0.75) 2(-1.4,0.25) 3(-1.4,-0.25) 4(-1.4,-0.75) 5(1.4,-0.75) 6(1.4,-0.25) 7(1.4,0.25) 8(1.4,0.75)
  rect 1.6x1.6 smd: 9(0,0)
  silkscreen extent -1.9,-1.63 1.9,1.6, body extent -1.51,-1.5 1.51,1.5, height 0.8
JA4220-AL_ [mm]
  rect 0.76x1.2 smd mask+0.05: 1(-1.52,1.525) 2(1.52,1.5) 3(1.52,-1.525) 4(-1.52,-1.525) NC(0,1.525) NC(0,-1.525)
  silkscreen extent -2.3,-0.7 2.3,2.5, body extent -2.22,-2.09 2.23,2.1, height 3.03
LD39100PUR [mm]
  rect 0.5x0.7 smd mask+0.05: 1(-0.95,-1.4) 2(0,-1.4) 3(0.95,-1.4) 4(0.95,1.4) 5(0,1.4) 6(-0.95,1.4)
  rect 2.5x1.7 smd mask+0.05: PAD(0,0)
  silkscreen extent -1.6,-1.6 1.6,1.6, body extent -1.5,-1.55 1.5,1.55, height 0.8
LED-2x0603 [mm]
  round 0.254 on Mech15: 0(0,0)
  rrect25% 0.7x0.4 smd: 1(-0.775,0.325) 2(-0.775,-0.375) 3(0.625,0.325) 4(0.625,-0.375)
  Top pour cut-out: -0.5,0.5 0.5,0.5 0.5,-0.5 -0.5,-0.5
  silkscreen extent -1.55,-0.95 1.68,0.9, body extent -0.8,-0.42 0.8,0.38, height 0.75
LED_RG_RIGHT_ANGLE_v2 [mm] "LTST-S326KGJRKT"
  round 0.254 on Mech14: 0(0,0)
  rrect25% 1.5x3 smd: A(-1.75,0.75) C1(1.75,0.75)
  rrect25% 0.9x2 smd: C2(0,1.25)
  Top pour cut-out: -1.025,1.15 1.025,1.15 1.025,-1.175 -1.025,-1.175
  silkscreen extent -2.7,-0.93 2.83,0.9, body extent -1.54,-1.47 1.46,0.52, height 1
LMK00105SQ [mm] "QFN, 24-Leads, Body 4,00x4,00mm, Pitch 0,50mm, Thermal Pad 2,60x2,60mm, IPC Medium Density"
  oval 0.9x0.25 smd mask+0.05: 1(-1.925,1.25) 2(-1.925,0.75) 3(-1.925,0.25) 4(-1.925,-0.25) 5(-1.925,-0.75) 6(-1.925,-1.25) 13(1.925,-1.25) 14(1.925,-0.75) 15(1.925,-0.25) 16(1.925,0.25) 17(1.925,0.75) 18(1.925,1.25)
  oval 0.25x0.9 smd mask+0.05: 7(-1.25,-1.925) 8(-0.75,-1.925) 9(-0.25,-1.925) 10(0.25,-1.925) 11(0.75,-1.925) 12(1.25,-1.925) 19(1.25,1.925) 20(0.75,1.925) 21(0.25,1.925) 22(-0.25,1.925) 23(-0.75,1.925) 24(-1.25,1.925)
  rect 2.6x2.6 smd mask+0.05: 25(0,0)
  silkscreen extent -2.83,-2.22 2.22,2.22, body extent -2,-2 2,2, height 1
LMS7002M_v4 [mm] "LMS7002 without AM2 pad (internally unconnected)"
  round 0.35 smd mask+0: A5(-3.998,5.49) A7(-3.332,5.49) A9(-2.666,5.49) A13(-1.334,5.49) A17(-0.002,5.49) A21(1.33,5.49) AA1(-5.33,-1.17) AA3(-4.664,-1.17) AA5(-3.998,-1.17) AA29(3.994,-1.17) AA31(4.66,-1.17) AA33(5.326,-1.17) AB2(-4.997,-1.503) AB4(-4.331,-1.503) AB6(-3.665,-1.503) AB30(4.327,-1.503) AB32(4.993,-1.503) AB34(5.659,-1.503) AC3(-4.664,-1.836) AC5(-3.998,-1.836) AC29(3.994,-1.836) AC31(4.66,-1.836) AC33(5.326,-1.836) AD2(-4.997,-2.169) AD4(-4.331,-2.169) AD6(-3.665,-2.169) AD30(4.327,-2.169) AD32(4.993,-2.169) AE1(-5.33,-2.502) AE3(-4.664,-2.502) AE5(-3.998,-2.502) AE29(3.994,-2.502) AE31(4.66,-2.502) AE33(5.326,-2.502) AF2(-4.997,-2.835) AF4(-4.331,-2.835) AF6(-3.665,-2.835) AF30(4.327,-2.835) AF32(4.993,-2.835) AF34(5.659,-2.835) AG3(-4.664,-3.168) AG5(-3.998,-3.168) AG29(3.994,-3.168) AG31(4.66,-3.168) AG33(5.326,-3.168) AH2(-4.997,-3.501) AH4(-4.331,-3.501) AH30(4.327,-3.501) AH32(4.993,-3.501) AJ1(-5.33,-3.834) AJ3(-4.664,-3.834) AJ5(-3.998,-3.834) AJ7(-3.332,-3.834) AJ9(-2.666,-3.834) AJ11(-2,-3.834) AJ13(-1.334,-3.834) AJ15(-0.668,-3.834) AJ19(0.664,-3.834) AJ21(1.33,-3.834) AJ25(2.662,-3.834) AJ27(3.328,-3.834) AJ29(3.994,-3.834) AJ31(4.66,-3.834) AJ33(5.326,-3.834) AK2(-4.997,-4.167) AK4(-4.331,-4.167) AK6(-3.665,-4.167) AK8(-2.999,-4.167) AK10(-2.333,-4.167) AK12(-1.667,-4.167) AK14(-1.001,-4.167) AK20(0.997,-4.167) AK22(1.663,-4.167) AK26(2.995,-4.167) AK28(3.661,-4.167) AK30(4.327,-4.167) AK32(4.993,-4.167) AK34(5.659,-4.167) AL3(-4.664,-4.5) AL5(-3.998,-4.5) AL7(-3.332,-4.5) AL9(-2.666,-4.5) AL11(-2,-4.5) AL13(-1.334,-4.5) AL19(0.664,-4.5) AL21(1.33,-4.5) AL23(1.996,-4.5) AL27(3.328,-4.5) AL29(3.994,-4.5) AL31(4.66,-4.5) AL33(5.326,-4.5) AM4(-4.331,-4.833) AM6(-3.665,-4.833) AM8(-2.999,-4.833) AM10(-2.333,-4.833) AM12(-1.667,-4.833) AM18(0.331,-4.833) AM20(0.997,-4.833) AM22(1.663,-4.833) AM24(2.329,-4.833) AM26(2.995,-4.833) AM28(3.661,-4.833) AM30(4.327,-4.833) AM34(5.659,-4.833) AN3(-4.664,-5.166) AN5(-3.998,-5.166) AN7(-3.332,-5.166) AN9(-2.666,-5.166) AN11(-2,-5.166) AN17(-0.002,-5.166) AN23(1.996,-5.166) AN25(2.662,-5.166) AN27(3.328,-5.166) AN29(3.994,-5.166) AN31(4.66,-5.166) AP6(-3.665,-5.499) AP10(-2.333,-5.499) AP26(2.995,-5.499) AP30(4.327,-5.499) AP32(4.993,-5.499) B2(-4.997,5.157) B4(-4.331,5.157) B8(-2.999,5.157) B10(-2.333,5.157) B12(-1.667,5.157) B14(-1.001,5.157) B16(-0.335,5.157) B18(0.331,5.157) B20(0.997,5.157) B22(1.663,5.157) C1(-5.33,4.824) C3(-4.664,4.824) C5(-3.998,4.824) C7(-3.332,4.824) C9(-2.666,4.824) C11(-2,4.824) C13(-1.334,4.824) C15(-0.668,4.824) C17(-0.002,4.824) C19(0.664,4.824) C21(1.33,4.824) C23(1.996,4.824) C25(2.662,4.824) C27(3.328,4.824) C29(3.994,4.824) C31(4.66,4.824) D2(-4.997,4.491) D4(-4.331,4.491) D6(-3.665,4.491) D8(-2.999,4.491) D10(-2.333,4.491) D12(-1.667,4.491) D14(-1.001,4.491) D16(-0.335,4.491) D18(0.331,4.491) D20(0.997,4.491) D22(1.663,4.491) D24(2.329,4.491) D26(2.995,4.491) D28(3.661,4.491) D30(4.327,4.491) D32(4.993,4.491) E3(-4.664,4.158) E5(-3.998,4.158) E9(-2.666,4.158) E11(-2,4.158) E13(-1.334,4.158) E15(-0.668,4.158) E17(-0.002,4.158) E19(0.664,4.158) E21(1.33,4.158) E23(1.996,4.158) E25(2.662,4.158) E27(3.328,4.158) E29(3.994,4.158) E31(4.66,4.158) F2(-4.997,3.825) F4(-4.331,3.825) F6(-3.665,3.825) F8(-2.999,3.825) F10(-2.333,3.825) F12(-1.667,3.825) F14(-1.001,3.825) F16(-0.335,3.825) F18(0.331,3.825) F20(0.997,3.825) F22(1.663,3.825) F24(2.329,3.825) F26(2.995,3.825) F28(3.661,3.825) F30(4.327,3.825) F32(4.993,3.825) G1(-5.33,3.492) G3(-4.664,3.492) G5(-3.998,3.492) G29(3.994,3.492) G31(4.66,3.492) H2(-4.997,3.159) H6(-3.665,3.159) H30(4.327,3.159) H32(4.993,3.159) J1(-5.33,2.826) J3(-4.664,2.826) J5(-3.998,2.826) J31(4.66,2.826) J33(5.326,2.826) K2(-4.997,2.493) K4(-4.331,2.493) K6(-3.665,2.493) K30(4.327,2.493) K32(4.993,2.493) K34(5.659,2.493) L3(-4.664,2.16) L5(-3.998,2.16) L31(4.66,2.16) L33(5.326,2.16) M2(-4.997,1.827) M4(-4.331,1.827) M6(-3.665,1.827) M30(4.327,1.827) M32(4.993,1.827) N1(-5.33,1.494) N3(-4.664,1.494) N31(4.66,1.494) N33(5.326,1.494) P2(-4.997,1.161) P4(-4.331,1.161) P30(4.327,1.161) P32(4.993,1.161) P34(5.659,1.161) R3(-4.664,0.828) R5(-3.998,0.828) R29(3.994,0.828) R31(4.66,0.828) R33(5.326,0.828) T4(-4.331,0.495) T6(-3.665,0.495) T30(4.327,0.495) T32(4.993,0.495) U1(-5.33,0.162) U3(-4.664,0.162) U5(-3.998,0.162) U29(3.994,0.162) U31(4.66,0.162) U33(5.326,0.162) V2(-4.997,-0.171) V4(-4.331,-0.171) V6(-3.665,-0.171) V30(4.327,-0.171) V32(4.993,-0.171) V34(5.659,-0.171) W3(-4.664,-0.504) W29(3.994,-0.504) W31(4.66,-0.504) W33(5.326,-0.504) Y2(-4.997,-0.837) Y4(-4.331,-0.837) Y6(-3.665,-0.837) Y30(4.327,-0.837) Y32(4.993,-0.837)
  rect 0.2x0.2 smd: GND(0.175,0.025)
  Top region: -3.325,-3.5 3.675,-3.5 3.675,3.5 -3.325,3.5
  silkscreen extent -6.1,-6.3 6.4,6.2, body extent -5.6,-5.75 5.9,5.75, height 0.97
LXDC55K [mm] "LXDC55K"
  rect 0.7x1.1 smd mask+0.05: 1(2.2,1.6) 2(1.1,1.6) 3(0,1.6) 4(-1.1,1.6) 5(-2.2,1.6) 6(-2.2,0) 7(-2.2,-1.7) 8(-1.1,-1.7) 9(0,-1.7) 10(1.1,-1.7) 11(2.2,-1.7) 12(2.2,0) 13(0,0) 14(-1.1,0)
  silkscreen extent -2.65,-2.2 3.03,2.1, body extent -2.85,-2.5 2.85,2.5, height 2.1
M24128S [mm]
  round 0.21 smd mask+0.05: A1(-0.25,0.2) A2(0.25,0.2) B1(-0.25,-0.2) B2(0.25,-0.2)
  silkscreen extent -0.84,-0.5 0.6,0.5, body extent -0.41,-0.35 0.41,0.35, height 0.33
MMCX_UFL_conn_u [mm]
  rect 1.2x1.2 smd mask+0.05: 1(0,1.6) 2(0,-1.6)
  rect 1.55x1 smd mask+0.05: 1(0,1.7) 2(0,-1.7)
  rect 1.2x1.6 smd mask+0.05: 2(-1.7,0) 2(1.7,0)
  rect 1.2x2.15 smd mask+0.05: 2(-1.4,0) 2(1.4,0)
  silkscreen extent -2.3,-2.2 2.3,2.2, body extent -1.5,-1.55 1.5,1.55, height 1.25
NetTie_Wide2 [mm]
  rect 0.4x4 on Mid1: 1(-0.575,0) 2(0.575,0)
  L2 region: -0.775,2 -0.775,-2 0.775,-2 0.775,2
RAKON_RTX5032A [mm] "RAKON RTX5032A 40MHz Filter enabled, with VC, 10pin 5mm x 3.2mm"
  rect 1.35x1 smd mask+0.05: 1(-1.925,-1.15) 4(1.925,-1.15) 6(1.925,1.15) 9(-1.925,1.15)
  rect 0.7x1.35 smd mask+0.05: 2(-0.6,-0.975) 3(0.6,-0.975) 7(0.6,0.975) 8(-0.6,0.975)
  rect 1.35x0.7 smd mask+0.05: 5(1.925,0) 10(-1.925,0)
  silkscreen extent -3.2,-2.25 2.8,1.85, body extent -2.5,-1.6 2.5,1.6, height 0.9
RES0201 [mm]
  rect 0.3x0.35 smd: 1(-0.28,0) 2(0.28,0)
  silkscreen extent -0.2,-0.33 0.2,0.33, body extent -0.3,-0.15 0.3,0.15, height 0.25
RES0402#1 [mm] "Chip Resistor, Body 1.0x0.5mm, EIA 0402, IPC Medium Density"
  round 0.2 on Mech15: 0(0,0)
  rrect20% 0.6x0.6 smd: 1(-0.5,0) 2(0.5,0)
  Top pour cut-out: -0.2,0.35 0.2,0.35 0.2,-0.35 -0.2,-0.35
  silkscreen extent -1.05,-0.55 1.05,0.55, body extent -0.52,-0.27 0.53,0.28, height 0.4
RES0402#2 [mm] "Chip Resistor, Body 1.0x0.5mm, EIA 0402, IPC Medium Density"
  round 0.2 on Mech14: 0(0,0)
  rrect20% 0.6x0.6 smd: 1(-0.5,0) 2(0.5,0)
  Top pour cut-out: -0.2,0.35 0.2,0.35 0.2,-0.35 -0.2,-0.35
  silkscreen extent -1.05,-0.55 1.05,0.55, body extent -0.52,-0.27 0.53,0.28, height 0.4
